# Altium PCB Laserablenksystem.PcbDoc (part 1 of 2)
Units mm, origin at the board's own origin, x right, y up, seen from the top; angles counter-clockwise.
Board outline 80 x 72 mm, 6 copper layers (L1 (Signal), L2 (GND), L3 (PWR), L4 (PWR), L5 (GND), L6 (Signal)), stack 1.637 mm thick; 152 components, 77 nets, 436 pads, 219 vias.
Unrouted connection lines stored in the file: 1.
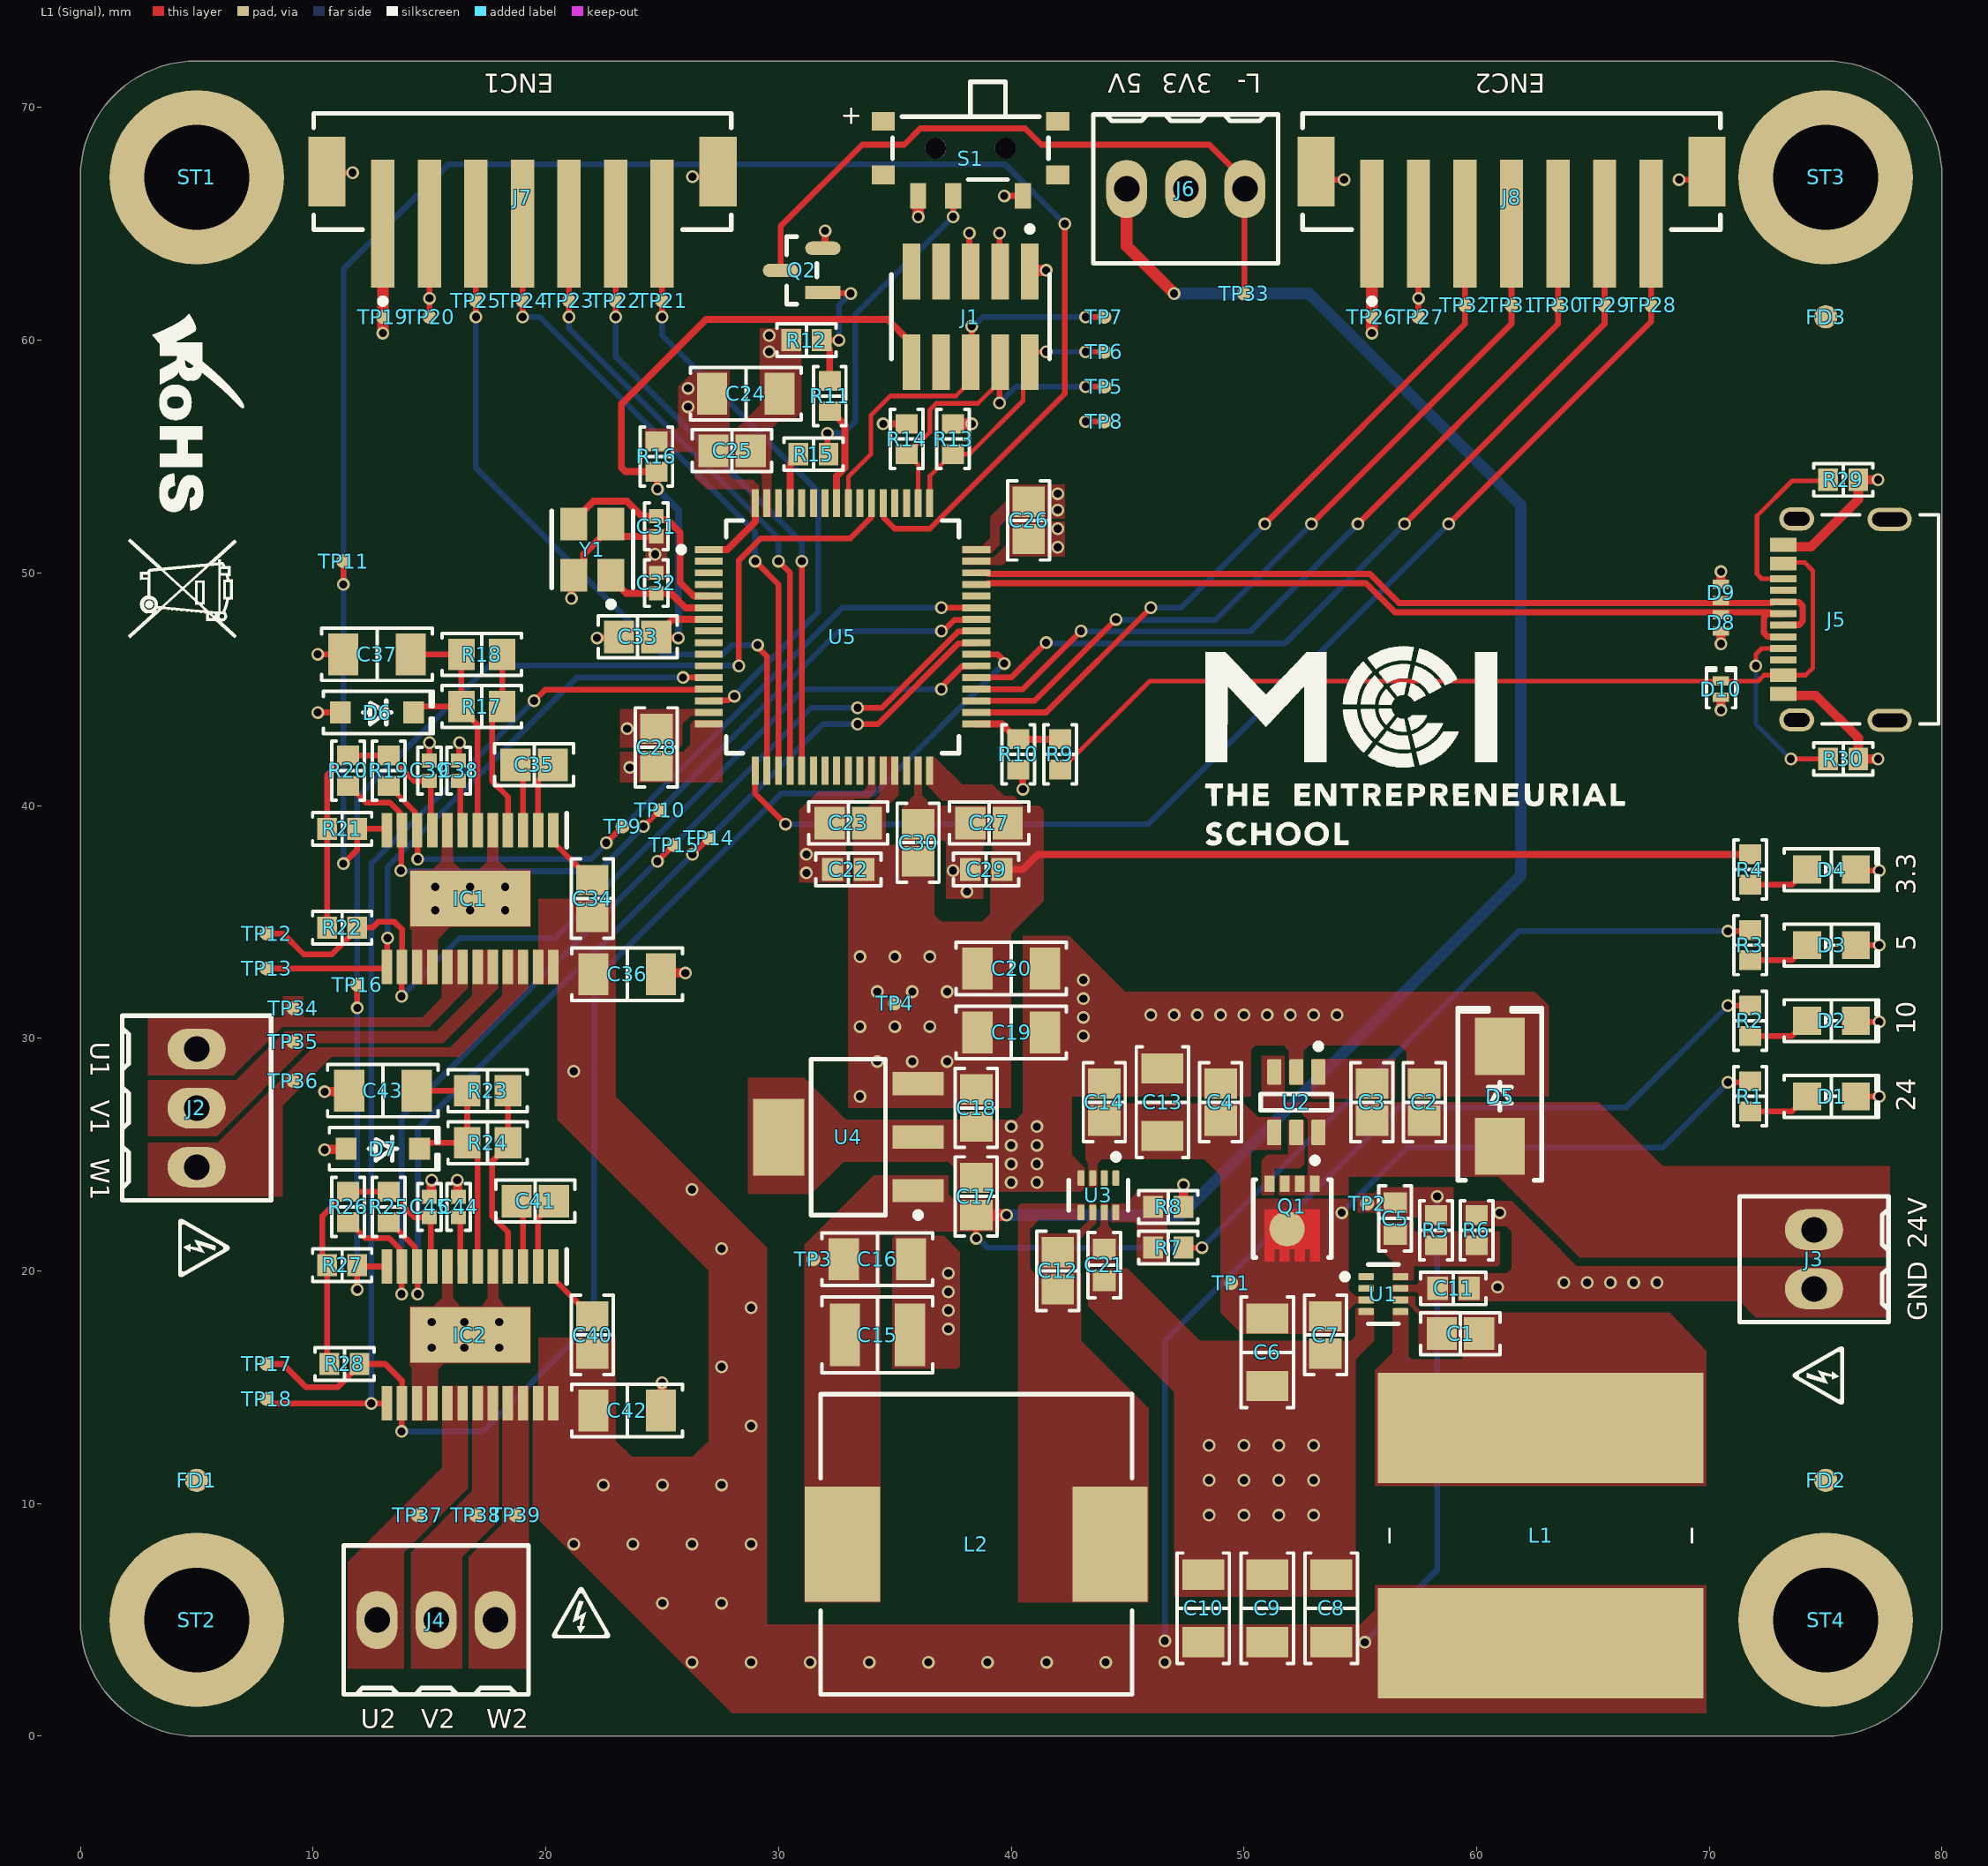
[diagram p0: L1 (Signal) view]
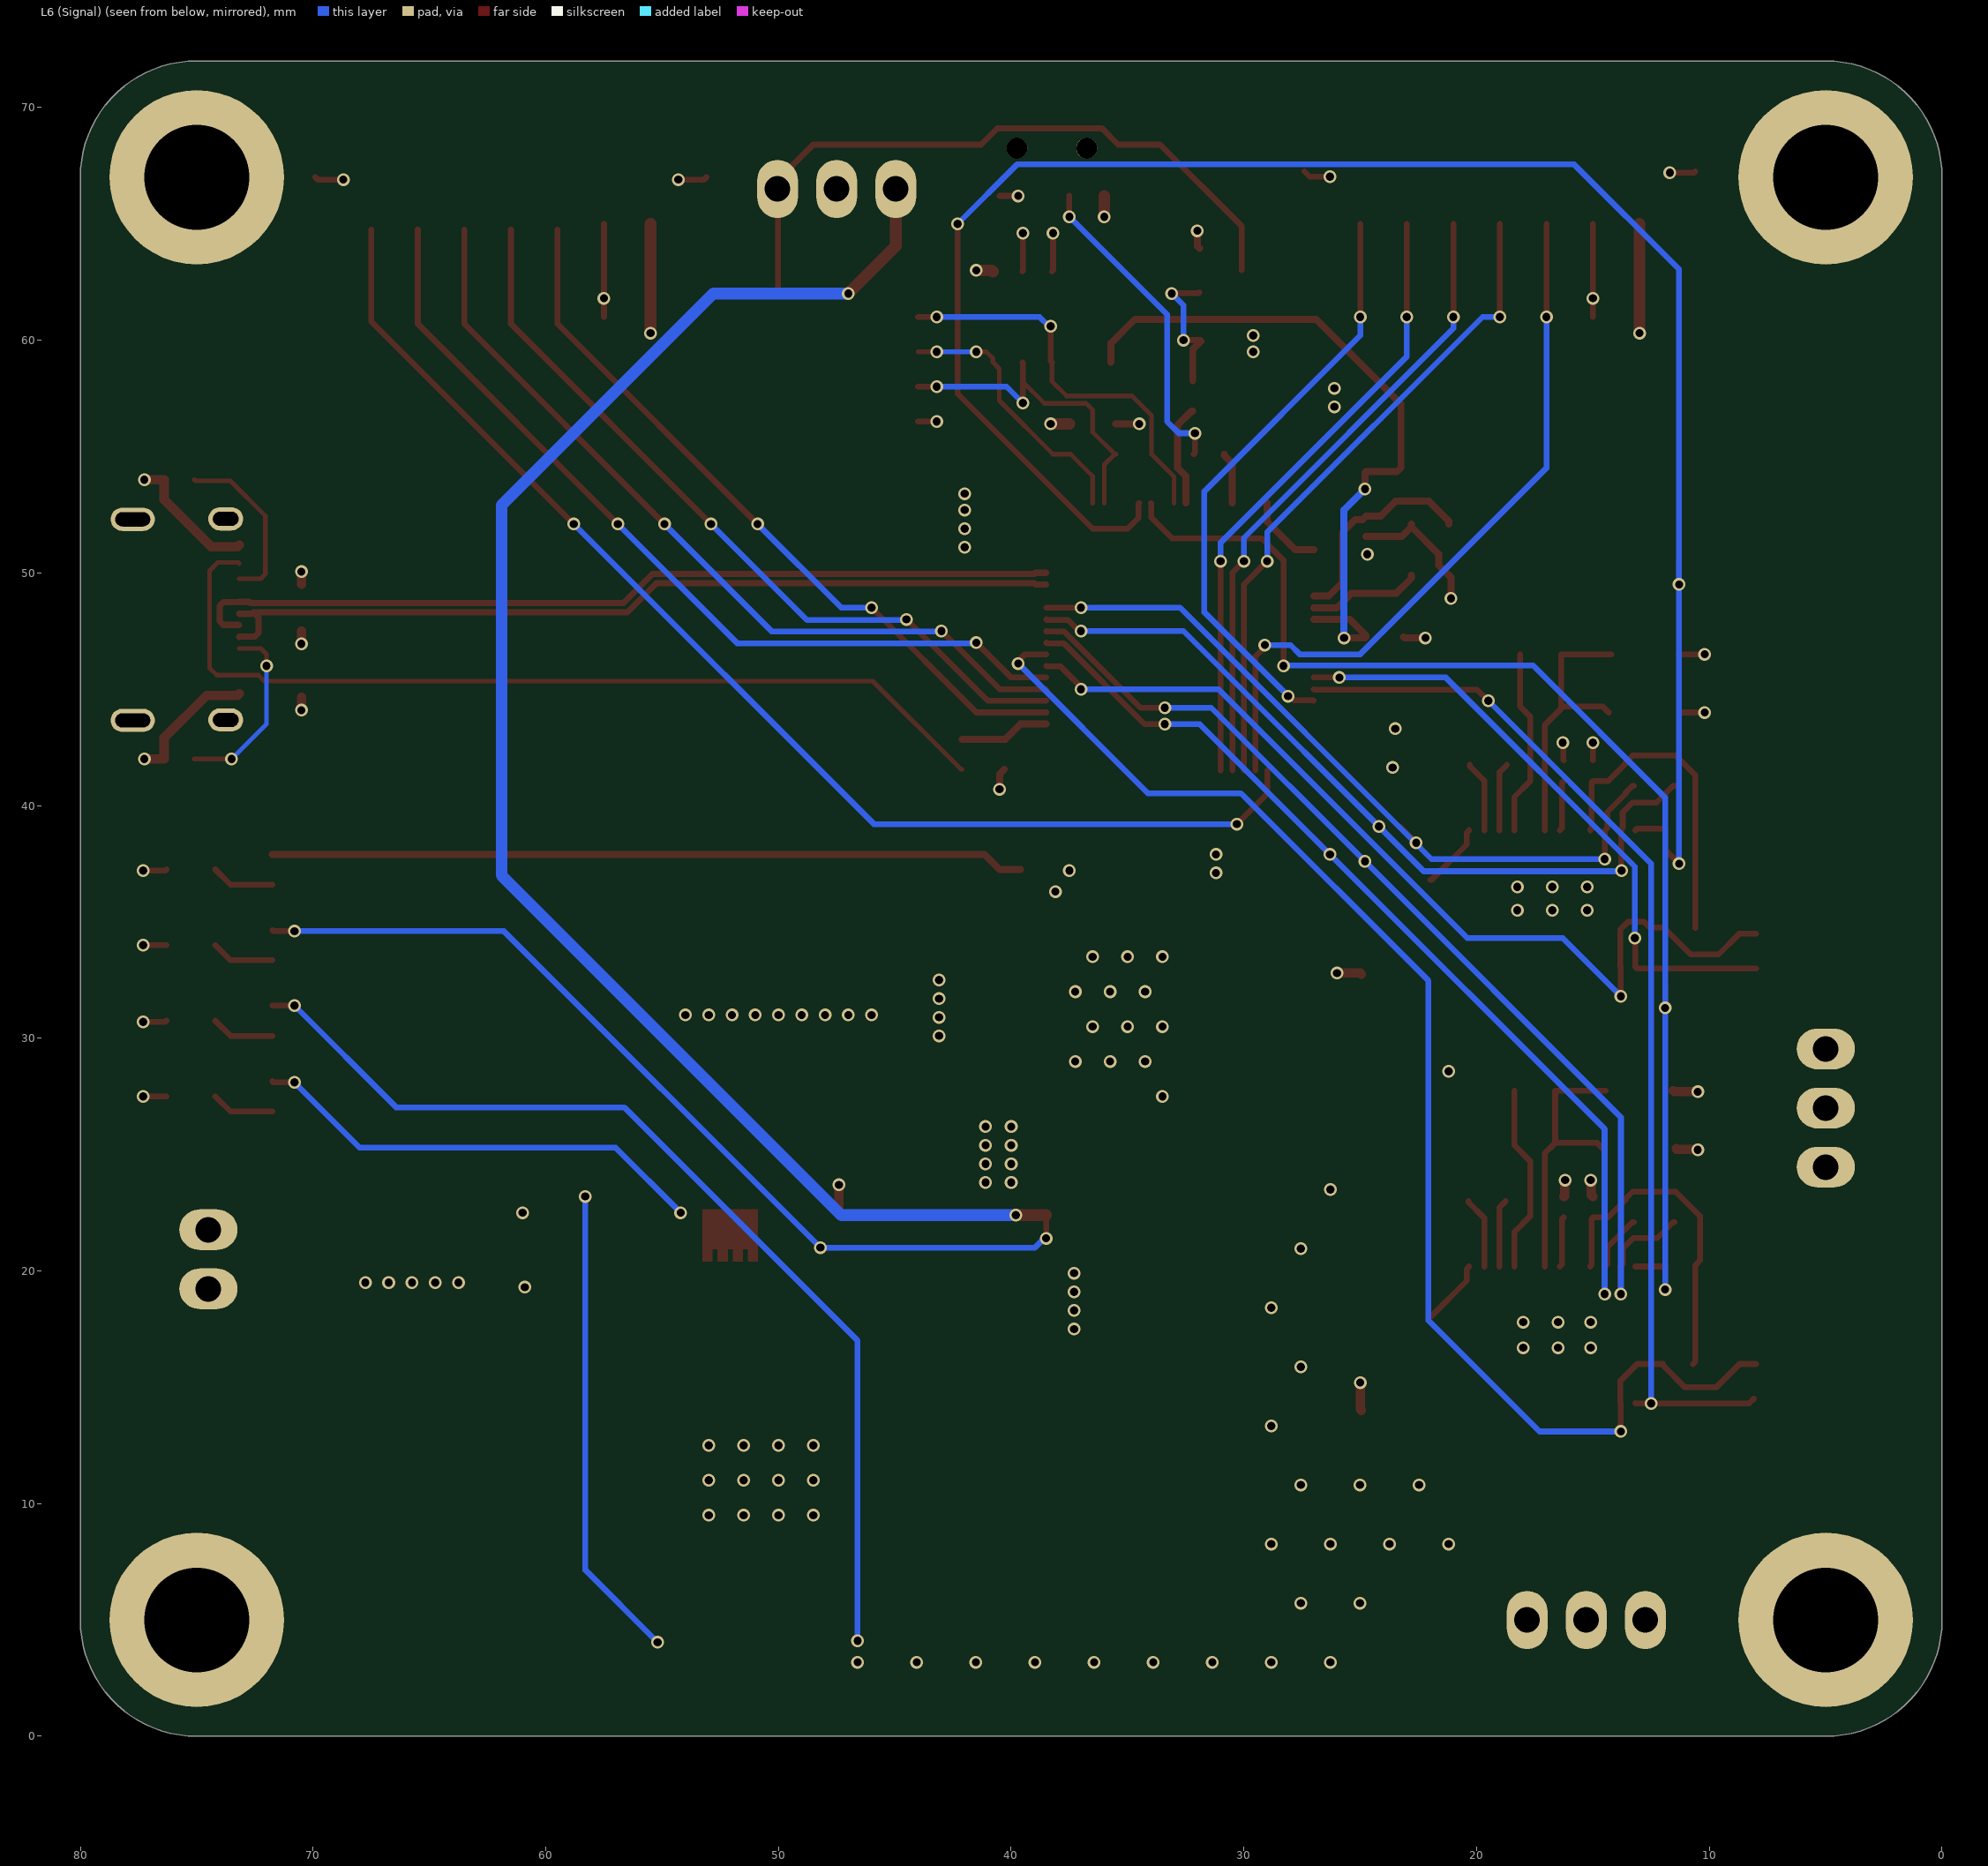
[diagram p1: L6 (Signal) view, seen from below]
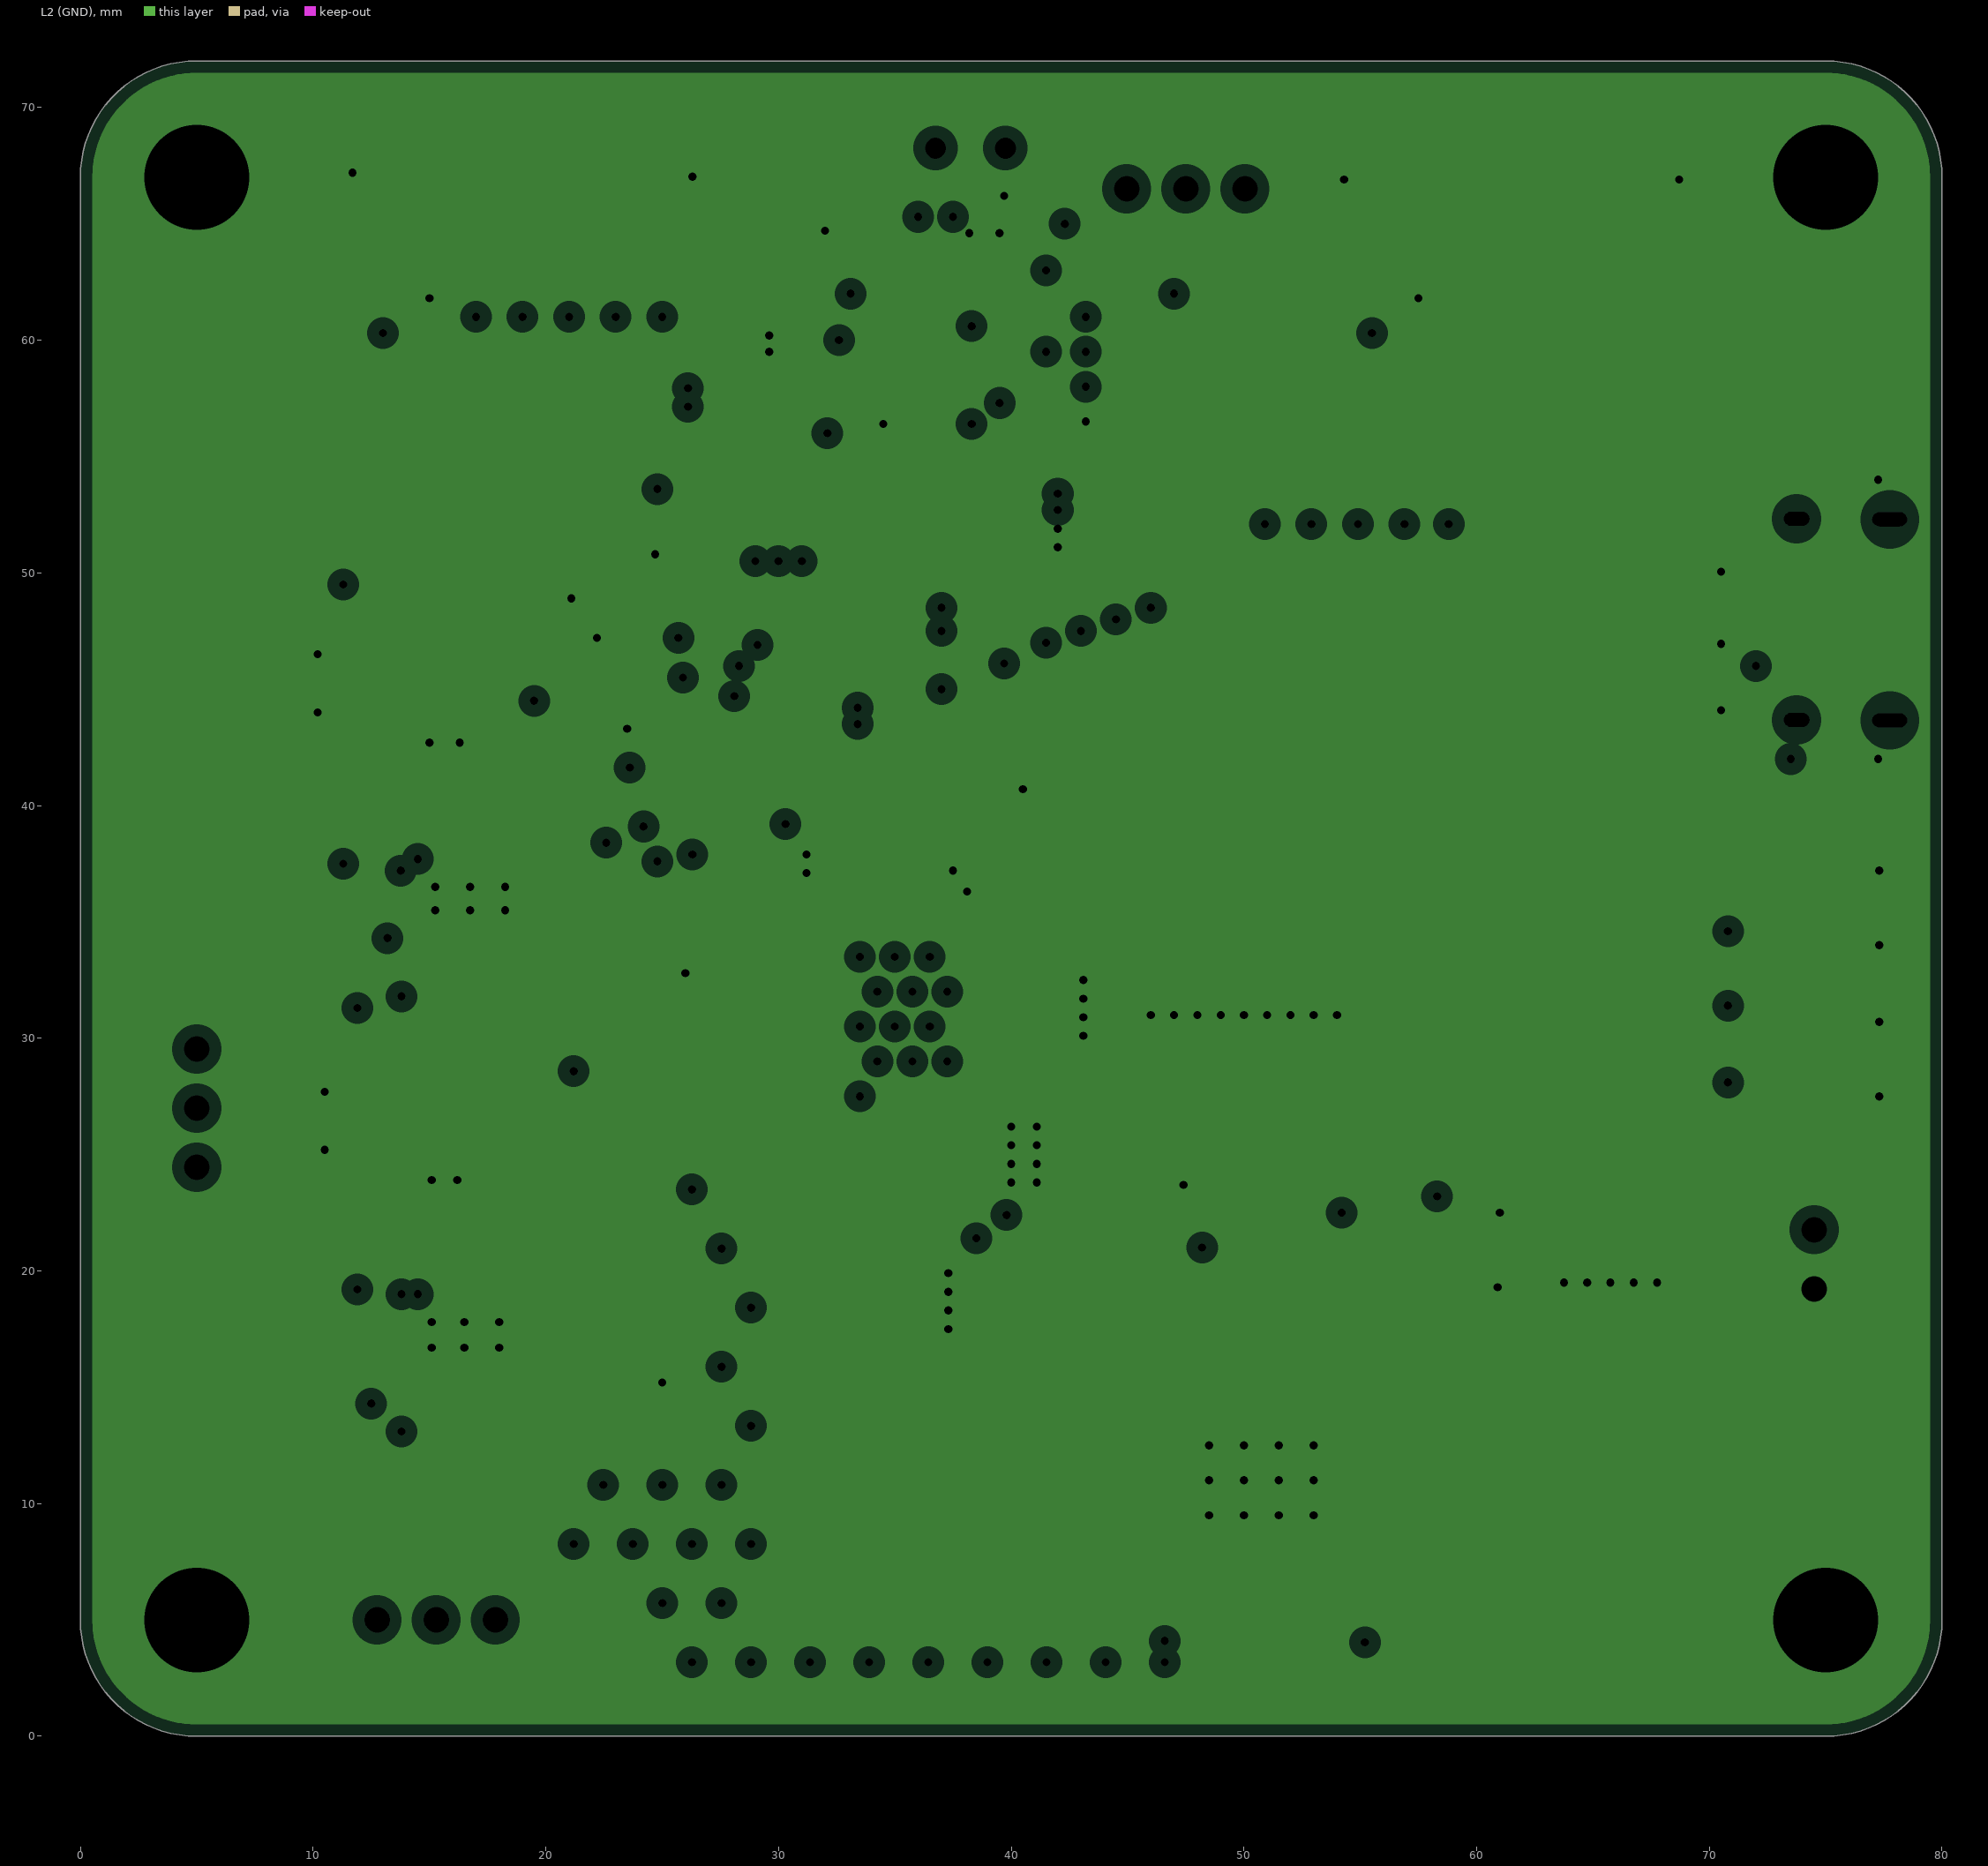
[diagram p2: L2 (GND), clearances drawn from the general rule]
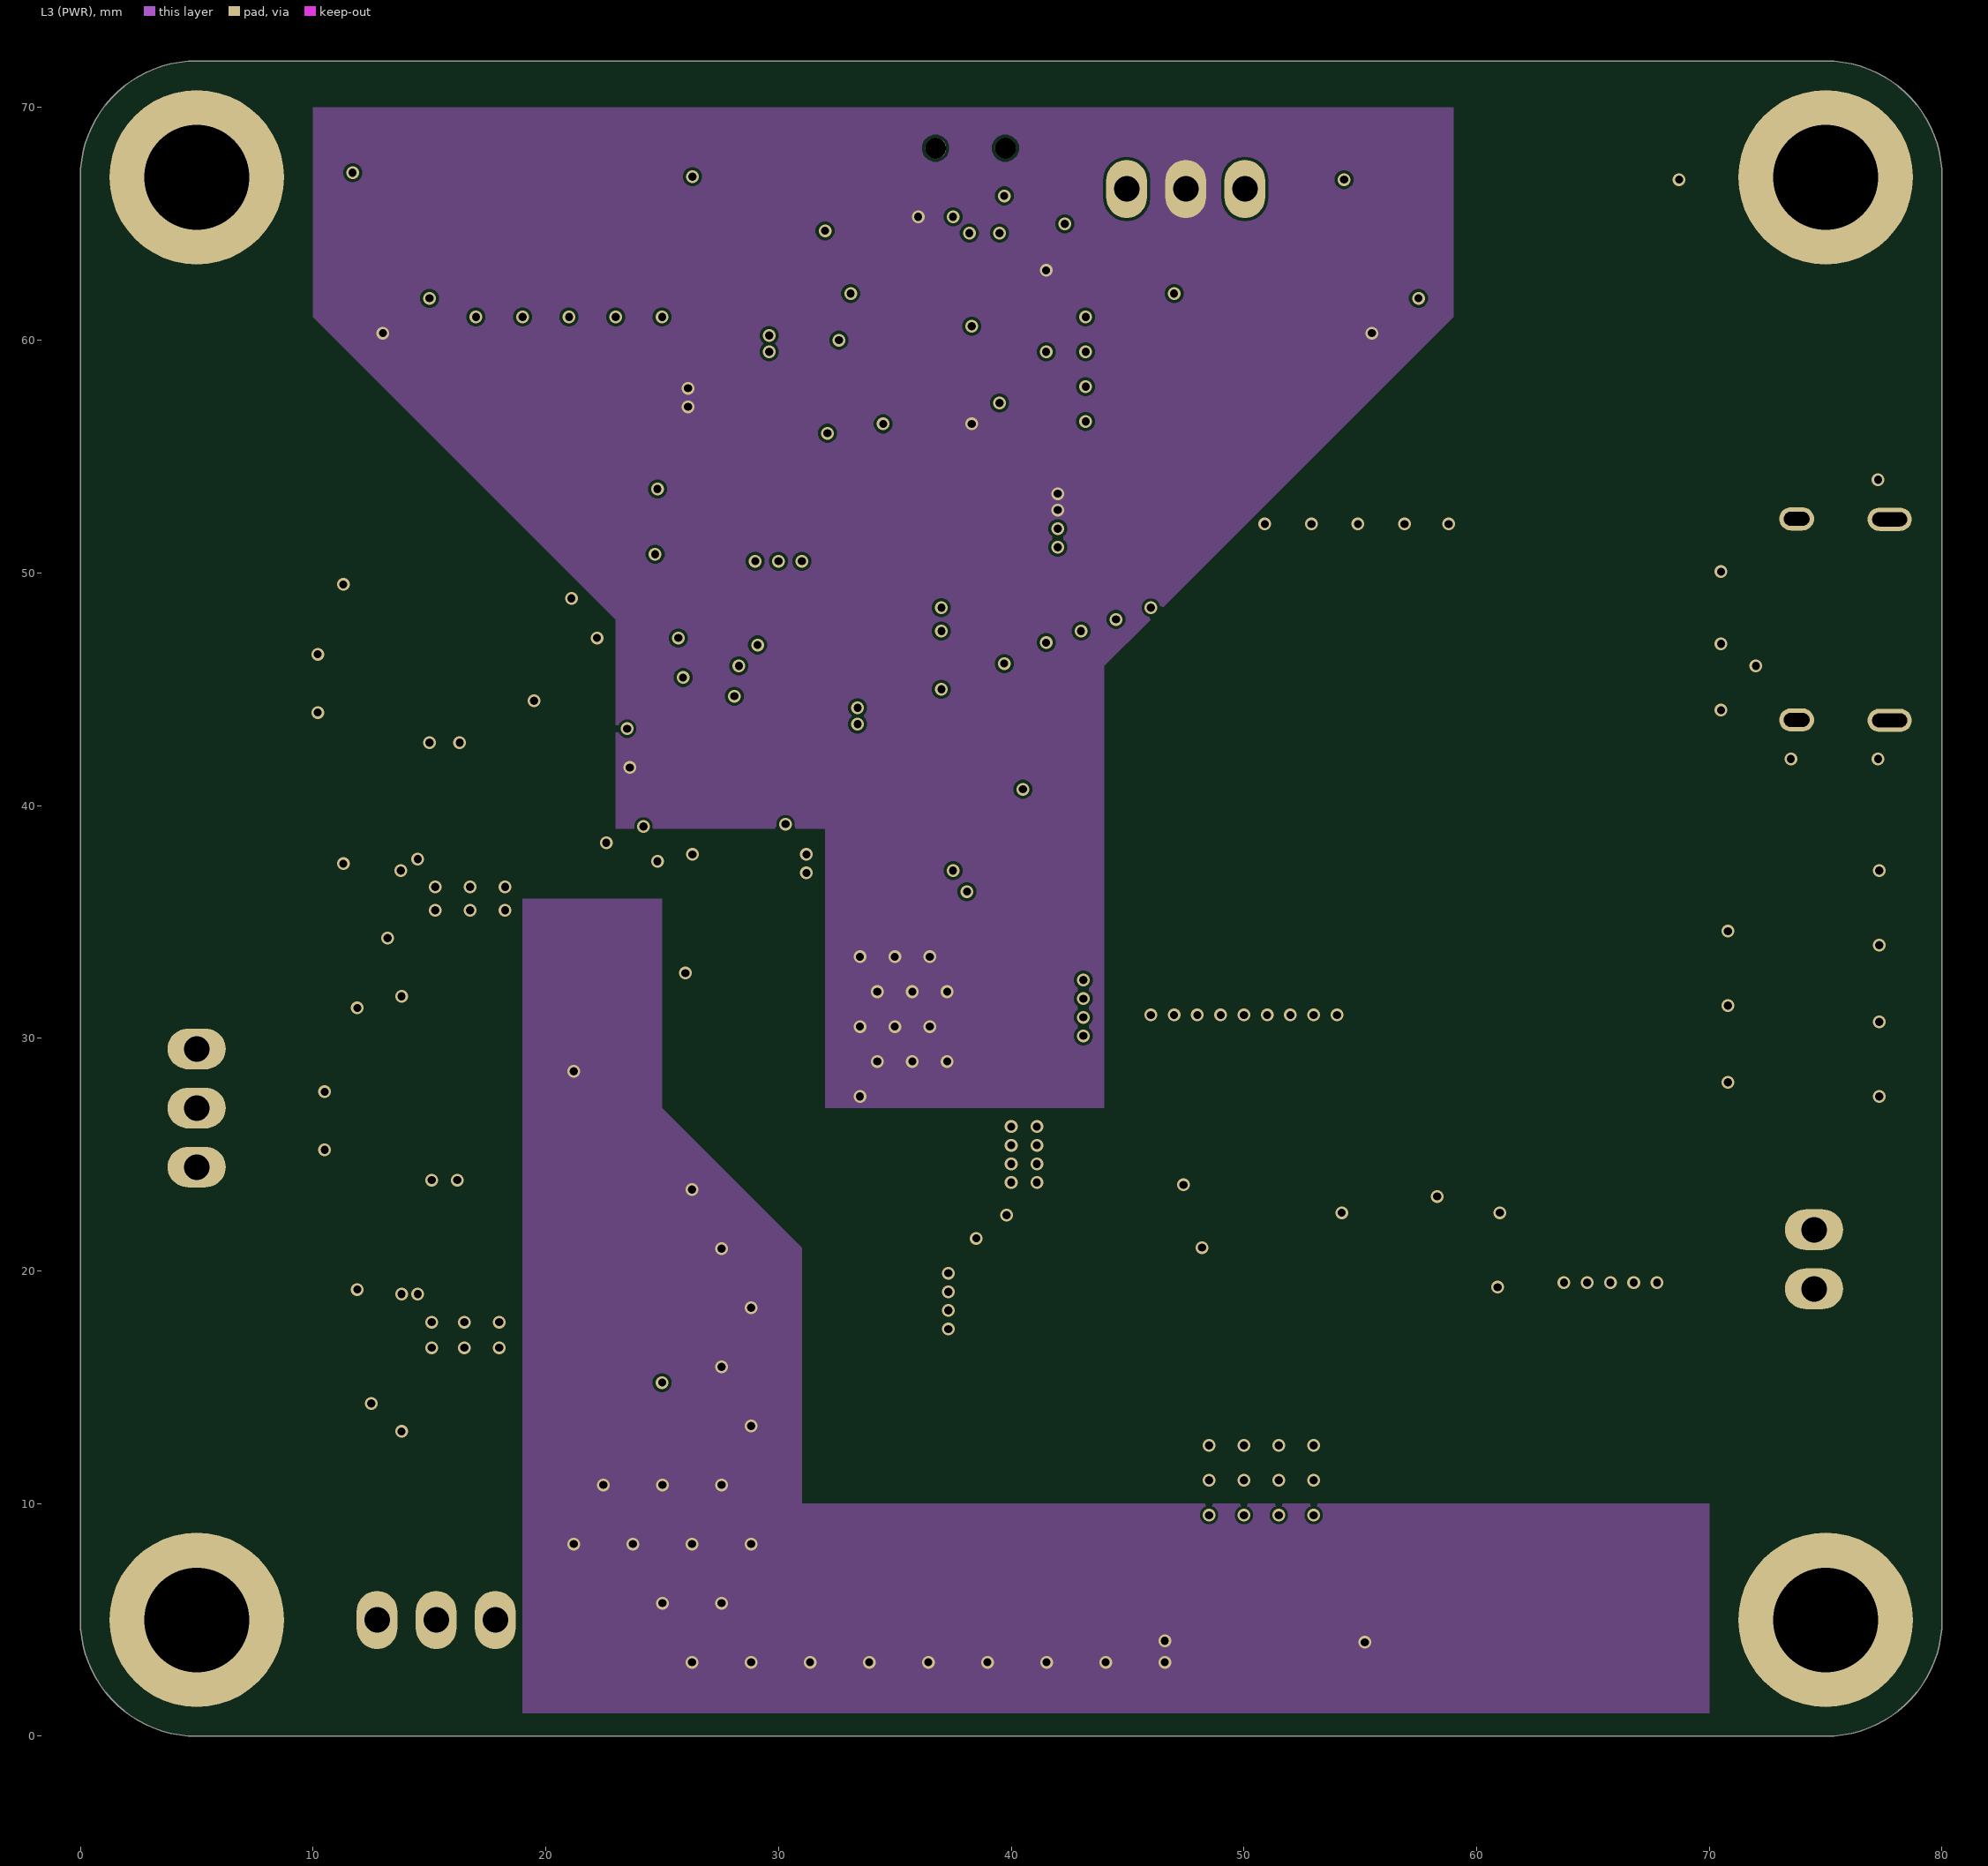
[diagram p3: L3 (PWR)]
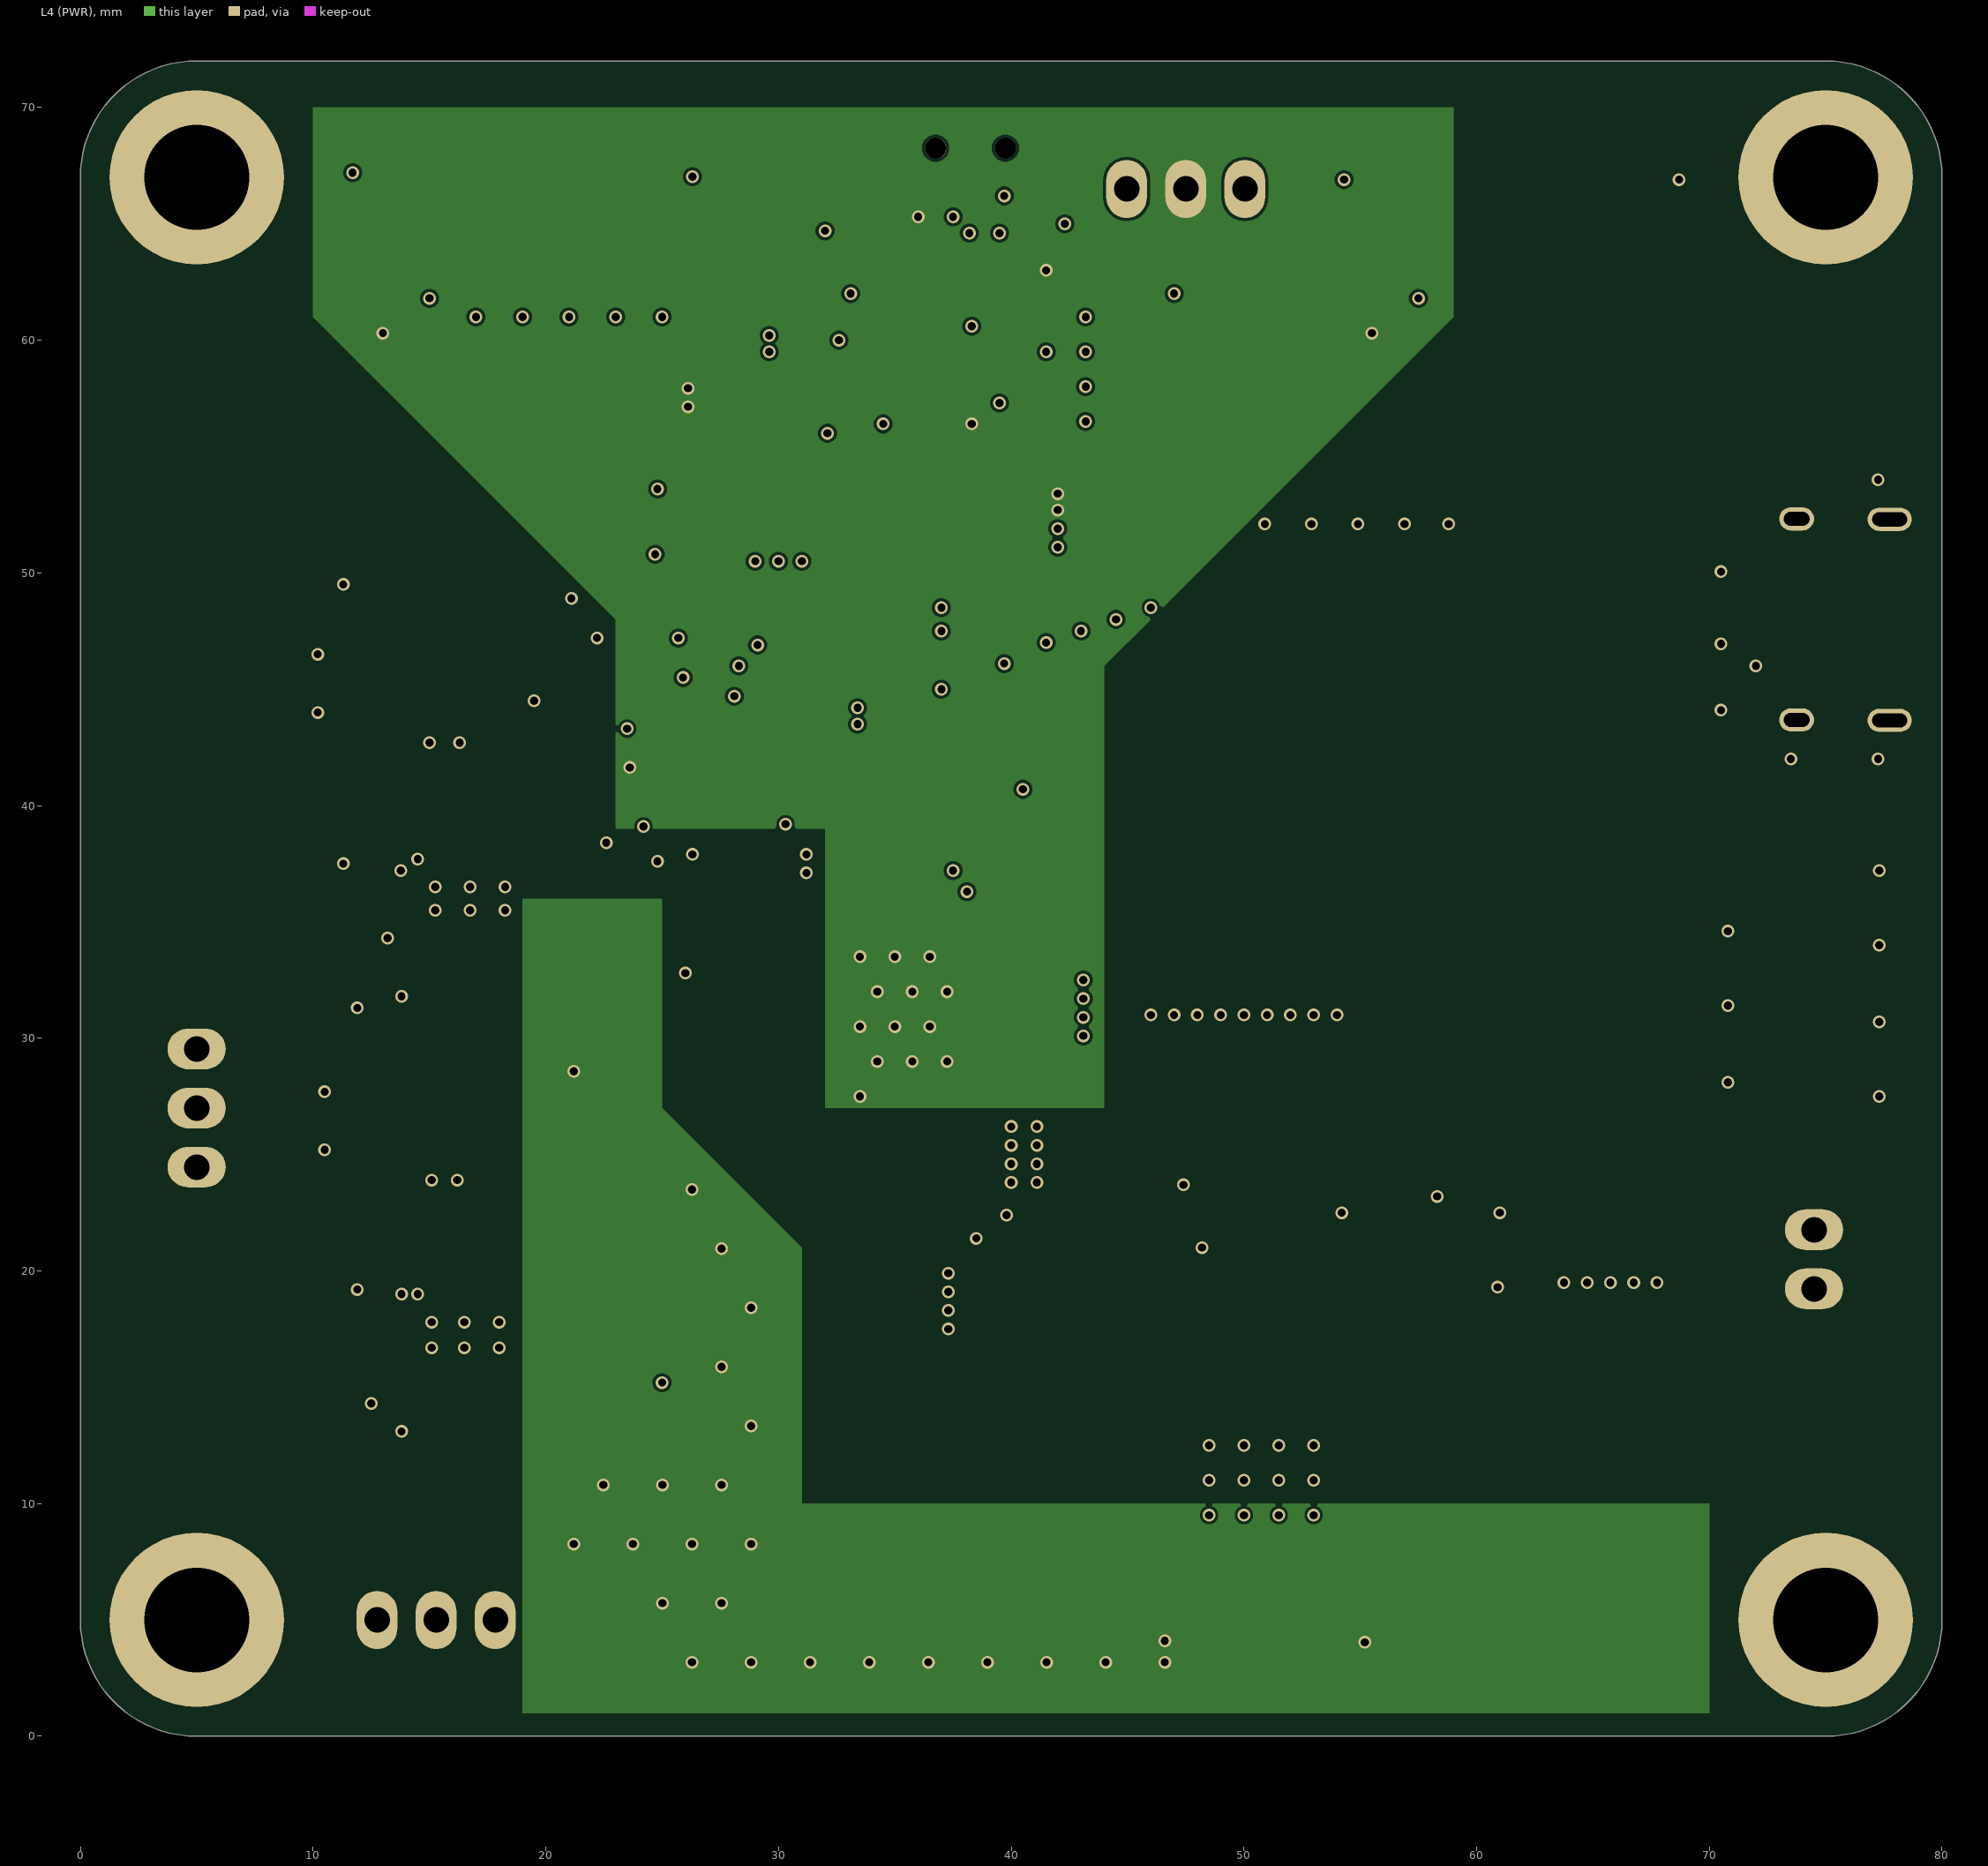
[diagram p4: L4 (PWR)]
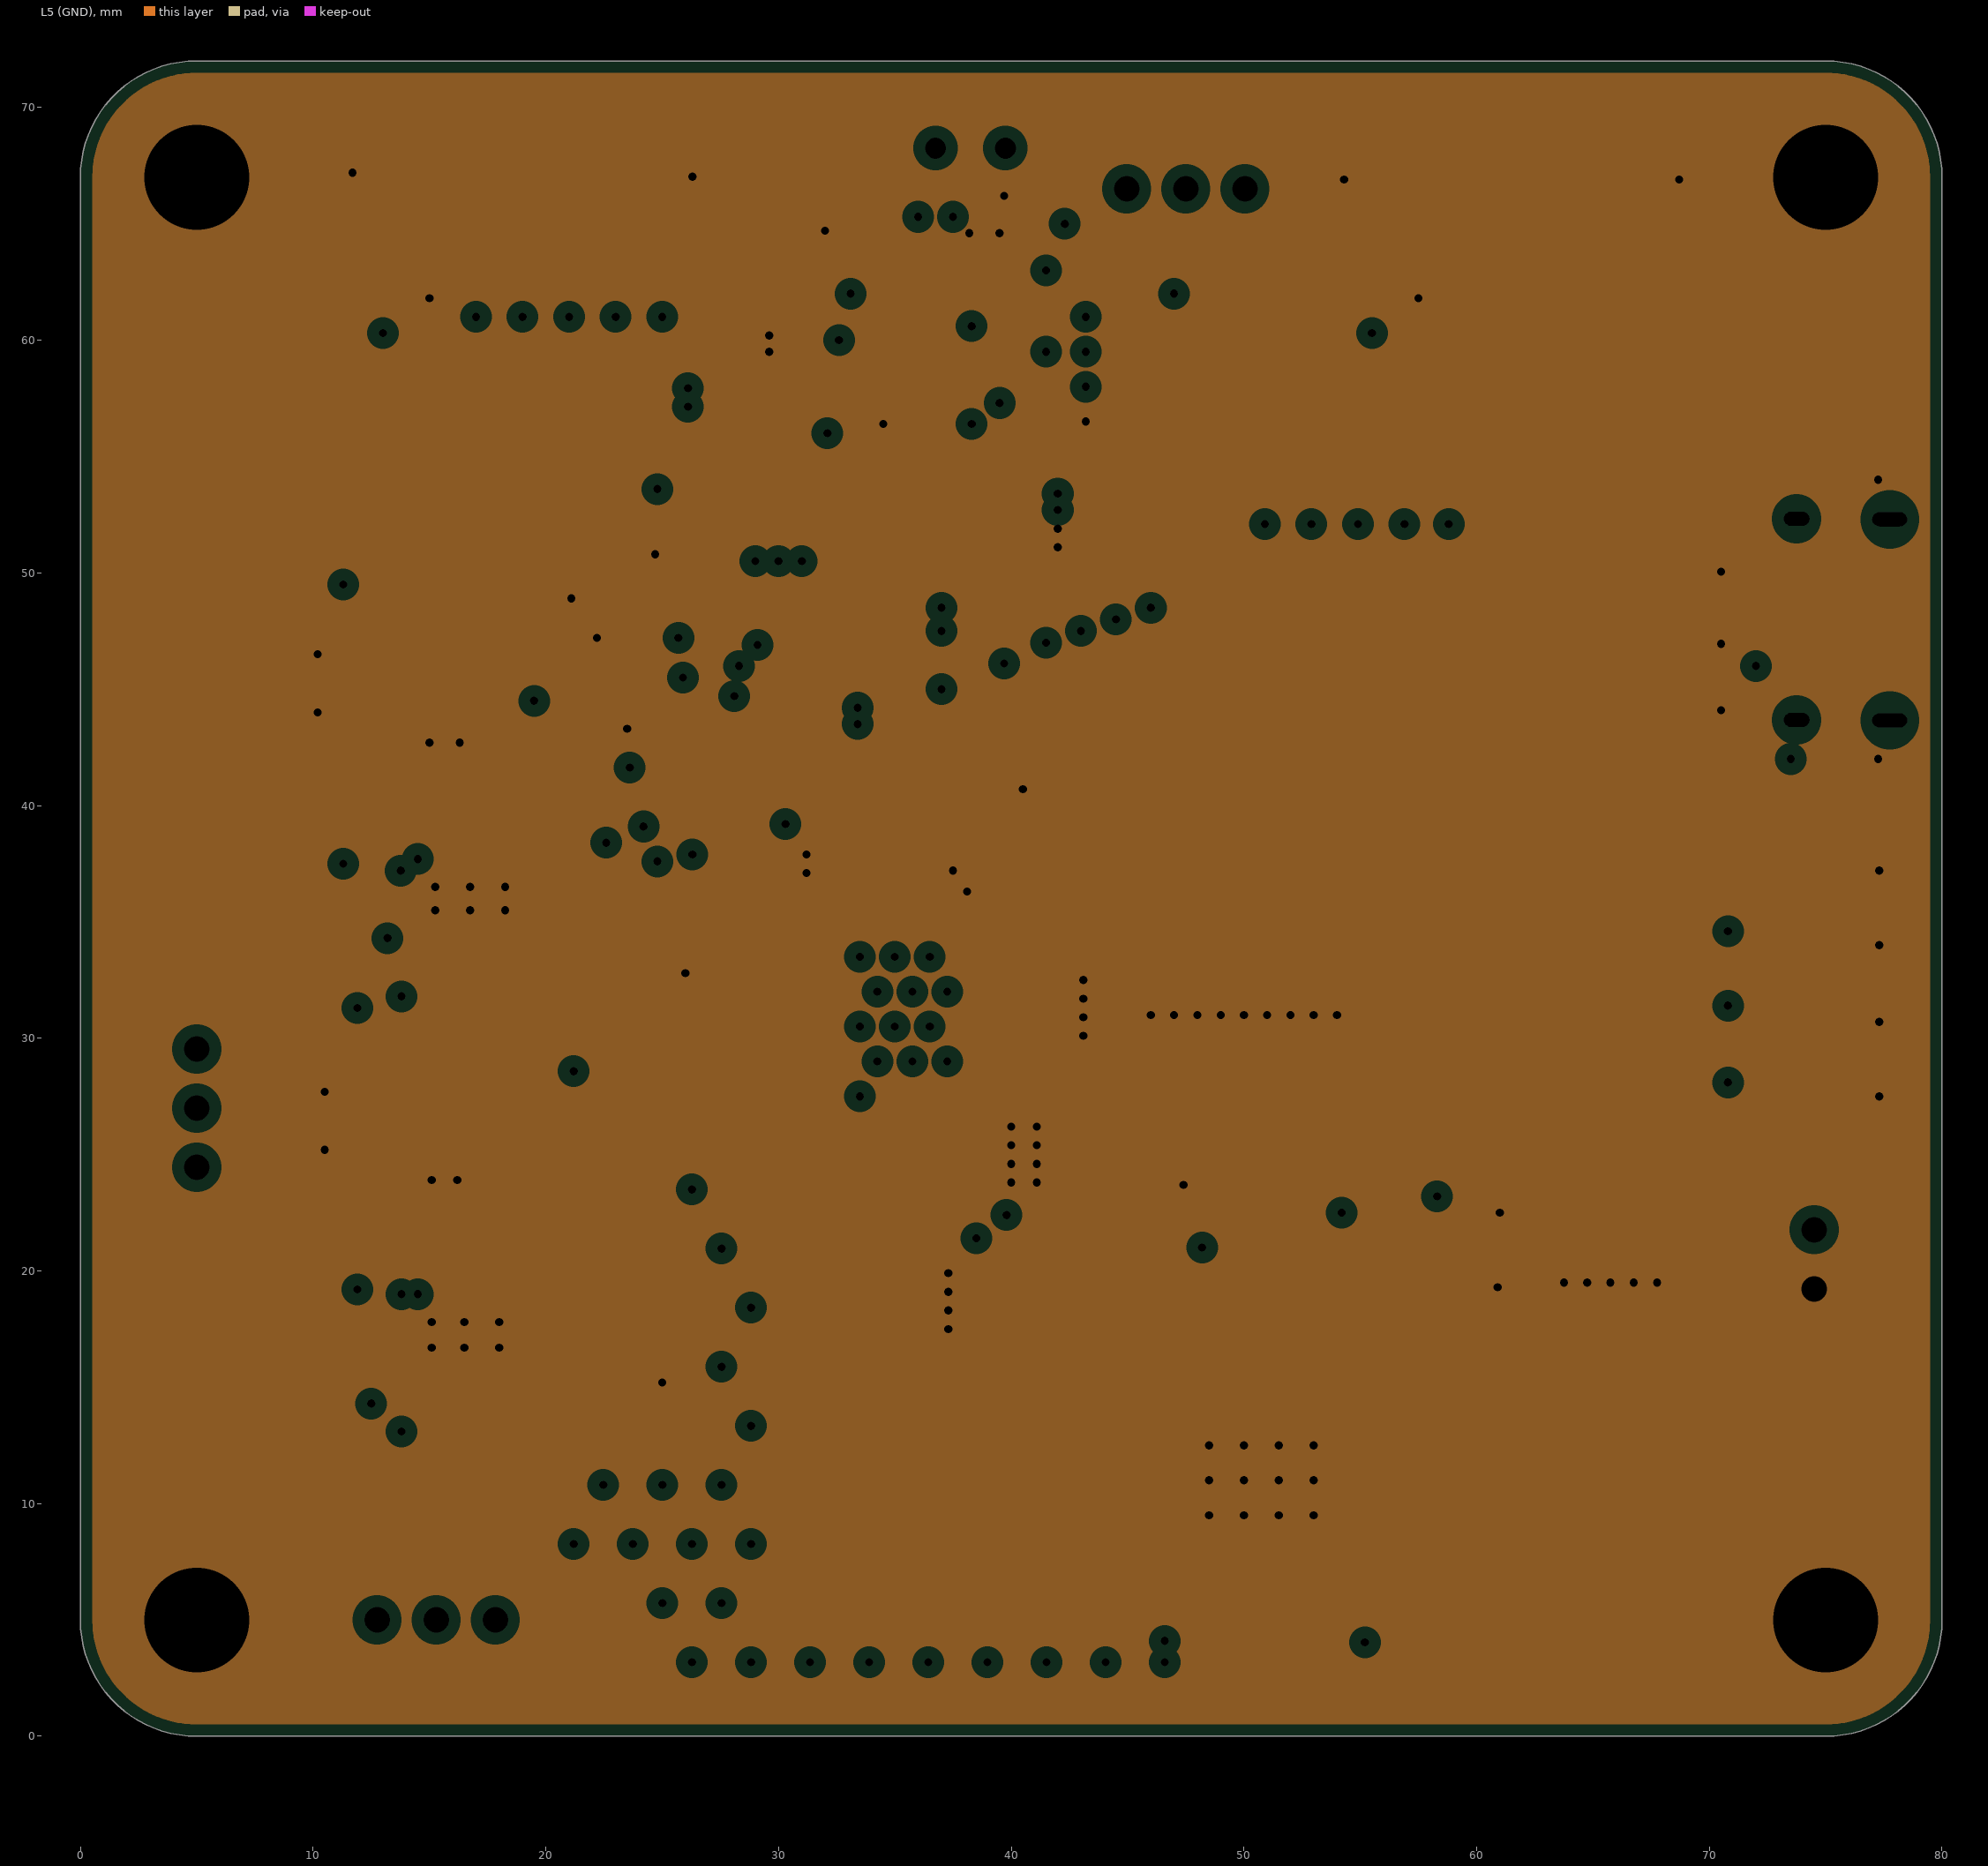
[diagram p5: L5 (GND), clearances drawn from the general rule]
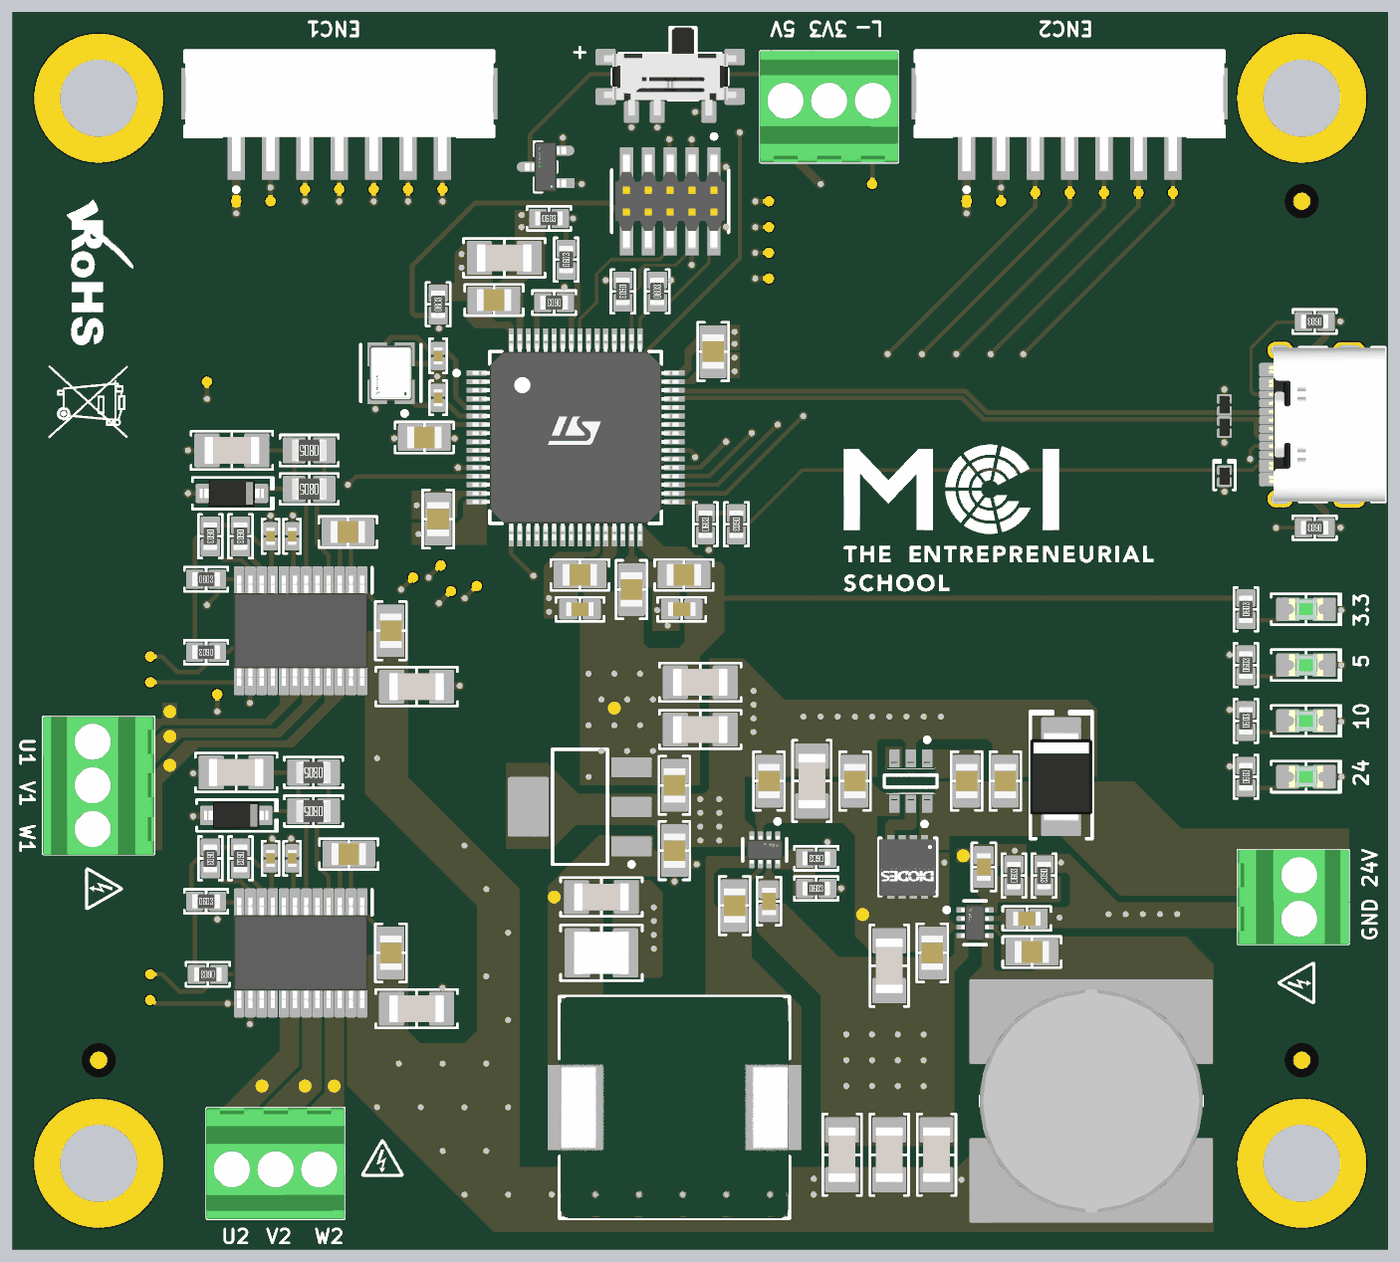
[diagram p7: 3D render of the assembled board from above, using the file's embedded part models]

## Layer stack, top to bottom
Top Solder: solder mask 0.0102, SM-001, Dk 3.5
L1 (Signal): signal copper 0.035
Dielectric 1: prepreg 0.1168, PP-016, Dk 4.25
Dielectric 2: prepreg 0.1168, PP-016, Dk 4.25
L2 (GND): plane copper 0.035, net GND
Dielectric 6: core 0.3048, Core-031, Dk 4.5
L3 (PWR): signal copper 0.035
Dielectric 8: prepreg 0.1168, PP-016, Dk 4.25
Dielectric 3: prepreg 0.1168, PP-016, Dk 4.25
Dielectric 9: prepreg 0.1168, PP-016, Dk 4.25
L4 (PWR): signal copper 0.035
Dielectric 7: core 0.3048, Core-031, Dk 4.5
L5 (GND): plane copper 0.035, net GND
Dielectric 4: prepreg 0.1168, PP-016, Dk 4.25
Dielectric 5: prepreg 0.1168, PP-016, Dk 4.25
L6 (Signal): signal copper 0.035
Bottom Solder: solder mask 0.0102, SM-001, Dk 3.5

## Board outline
0,5 0,50 0,67 cw(c5,67) 5,72 75,72 cw(c75,67) 80,67 80,5 cw(c75,5) 75,0 5,0 cw(c5,5)

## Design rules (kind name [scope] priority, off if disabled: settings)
Clearance [All] p1: gap=0.125 ignorepadtopadclearanceinfootprint=FALSE
DiffPairsRouting [All] p1: maxlimit=0.127 minlimit=0.127 mostfreqgap=0.127 toplayer_minwidth=0.27 toplayer_maxwidth=0.27 toplayer_prefwidth=0.27 midlayer1_minwidth=0.117 midlayer1_maxwidth=0.117 midlayer1_prefwidth=0.117 midlayer2_minwidth=0.117 midlayer2_maxwidth=0.117 midlayer2_prefwidth=0.117 bottomlayer_minwidth=0.27 bottomlayer_maxwidth=0.27 bottomlayer_prefwidth=0.27 impedanceprofiledriven=TRUE impedanceprofileid={E5E5535A-0CD5-4FF6-9C24-78283E052FCD} impedanceprofilevalue=90.000000 maxuncoupledlength=12.7
HoleSize HoleSizeVia [IsVia] p1: absolutevalues=TRUE maxlimit=0.45 minlimit=0.25 maxpercent=80.000 minpercent=20.000
HoleSize HoleSizePTH [IsPad] p2: absolutevalues=TRUE maxlimit=5.6 minlimit=0.5 maxpercent=80.000 minpercent=20.000
HoleToHoleClearance [All] p1: gap=0.3 allowstackedmicrovias=TRUE
MinimumAnnularRing MinimumAnnularRingVias [All] p1: minimumring=0.1
MinimumAnnularRing MinimumAnnularRingGeneral [All] p2: minimumring=0.3
MinimumSolderMaskSliver [All] p1: minsoldermaskwidth=0.08
PasteMaskExpansion [All] p1: expansion=0.085
PlaneClearance [All] p1: clearance=0.508
PlaneConnect [All] p1: planeconnectstyle=Direct reliefexpansion=0.508 reliefentries=4 reliefconductorwidth=0.254 reliefairgap=0.254
PolygonConnect [All] p1: connectstyle=Direct reliefconductorwidth=0.254 reliefentries=4 polygonreliefangle="90 Angle" airgapwidth=0.254
RoutingVias [All] p1: holewidth=0.35 width=0.55 viastyle="Through Hole" minholewidth=0.3 minwidth=0.5 maxholewidth=0.45 maxwidth=0.65
SilkToSilkClearance SilkToSilkClerance [All] p1: silktosilkclearance=0.125
SilkToSolderMaskClearance [IsPad] p1: minsilkscreentomaskgap=0.125 clearancetoexposedcopper=TRUE
SolderMaskExpansion SolderMaskExpansionVia [IsVia] p1: expansion=0.1 istentingtop=TRUE useseparateexpansions=TRUE expansionbottom=0.1 istentingbottom=TRUE
SolderMaskExpansion [All] p2: expansion=0.075 istentingtop=FALSE
SupplyNets "Schematic Supply Nets" [InNet('VCC3V3')] p1: voltage=0.000
SupplyNets "Schematic Supply Nets_6" [InNet('VCC24')] p2: voltage=0.000
SupplyNets "Schematic Supply Nets_5" [InNet('VCC5')] p3: voltage=0.000
SupplyNets "Schematic Supply Nets_3" [InNet('VCC10')] p4: voltage=0.000
SupplyNets "Schematic Supply Nets_1" [InNet('GND')] p5: voltage=0.000
UnRoutedNet [All] p1: checkbadconnections=TRUE
Width [All] p1: maxlimit=2.54 minlimit=0.125 preferedwidth=0.254
20 further rules are at their usual default settings.

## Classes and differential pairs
component class U_6_mech: FD1 FD2 FD3 ST1 ST2 ST3 ST4
component class U_5_conn: D8 D9 D10 J1 J2 J3 J4 J5 J6 J7 J8 R29 R30
component class U_4_motor-driver: C34 C35 C36 C37 C38 C39 C40 C41 C42 C43 C44 C45 D6 D7 IC1 IC2 R17 R18 R19 R20 R21 R22 R23 R24 R25 R26 R27 R28 TP34 TP35 TP36 TP37 TP38 TP39
component class U_3_mcu: C22 C23 C24 C25 C26 C27 C28 C29 C30 C31 C32 C33 Q2 R9 R10 R11 R12 R13 R14 R15 R16 S1 TP5 TP6 TP7 TP8 TP9 TP10 TP11 TP12 TP13 TP14 TP15 TP16 TP17 TP18 TP19 TP20 TP21 TP22 TP23 TP24 TP25 TP26 TP27 TP28 TP29 TP30 TP31 TP32 TP33 U5 Y1
component class U_2_power: C1 C2 C3 C4 C5 C6 C7 C8 C9 C10 C11 C12 C13 C14 C15 C16 C17 C18 C19 C20 C21 D5 L1 L2 Q1 R5 R6 R7 R8 TP1 TP2 TP3 TP4 U1 U2 U3 U4
component class 1_reference: D1 D2 D3 D4 R1 R2 R3 R4
differential pair USB: +USB_P -USB_N

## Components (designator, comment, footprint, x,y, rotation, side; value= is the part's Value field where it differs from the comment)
C1 "0.1 µF" "CAP 0805_2012" 59.3,17.3 r180 top
C2 "0.047µF" "CAP 0805_2012" 57.75,27.25 r270 top
C3 "0.1 µF" "CAP 0805_2012" 55.5,27.25 r270 top
C4 "0.1 µF" "CAP 0805_2012" 49,27.25 r270 top
C5 "1.5 pF" "CAP 0603_1608" 56.5,22.25 r90 top
C6 "10 µF" "CAP 1206_3216 - 0.8MM" 51,16.5 r90 top
C7 "0.1 µF" "CAP 0805_2012" 53.5,17.25 r90 top
C8 "10 µF" "CAP 1206_3216 - 0.8MM" 53.75,5.5 r270 top
C9 "10 µF" "CAP 1206_3216 - 0.8MM" 51,5.5 r270 top
C10 "10 µF" "CAP 1206_3216 - 0.8MM" 48.25,5.5 r270 top
C11 "0.033 µF" "CAP 0603_1608" 59,19.25 r180 top
C12 "0.1 µF" "CAP 0805_2012" 42,20 r90 top
C13 "10 µF" "CAP 1206_3216 - 0.8MM" 46.5,27.25 r270 top
C14 "0.1 µF" "CAP 0805_2012" 44,27.25 r270 top
C15 "47u" "CAP 1210_3225 - 1MM" 34.25,17.25 r180 top
C16 "10 µF" "CAP 1206_3216 - 0.8MM" 34.25,20.5 r180 top
C17 "0.1 µF" "CAP 0805_2012" 38.5,23.2 r270 top
C18 "0.1 µF" "CAP 0805_2012" 38.5,27 r90 top
C19 "10 µF" "CAP 1206_3216 - 0.8MM" 40,30.25 r180 top
C20 "10 µF" "CAP 1206_3216 - 0.8MM" 40,33 r180 top
C21 "0.033 µF" "CAP 0603_1608" 44,20.25 r90 top
C22 "1 µF" "CAP 0603_1608" 33,37.25 r0 top
C23 "0.1 µF" "CAP 0805_2012" 33,39.25 r0 top
C24 "4.7 µF" "CAP 1206_3216 - 0.8MM" 28.6,57.7 r180 top
C25 "0.1 µF" "CAP 0805_2012" 28,55.25 r180 top
C26 "0.1 µF" "CAP 0805_2012" 40.75,52.25 r90 top
C27 "0.1 µF" "CAP 0805_2012" 39.05,39.25 r0 top
C28 "0.1 µF" "CAP 0805_2012" 24.75,42.5 r270 top
C29 "1 µF" "CAP 0603_1608" 38.925,37.25 r0 top
C30 "0.1 µF" "CAP 0805_2012" 36,38.4 r270 top
C31 "9 pF" "CAP 0402_1005" 24.75,52 r90 top
C32 "9 pF" "CAP 0402_1005" 24.75,49.56 r270 top
C33 "0.1 µF" "CAP 0805_2012" 23.95,47.25 r0 top
C34 "0.1 µF" "CAP 0805_2012" 22,36 r90 top
C35 "0.1 µF" "CAP 0805_2012" 19.5,41.75 r180 top
C36 "10 µF" "CAP 1206_3216 - 0.8MM" 23.5,32.75 r0 top
C37 "10 µF" "CAP 1206_3216 - 0.8MM" 12.75,46.5 r0 top
C38 "1 µF" "CAP 0402_1005" 16.25,41.5 r90 top
C39 "1 µF" "CAP 0402_1005" 15,41.5 r90 top
C40 "0.1 µF" "CAP 0805_2012" 22,17.25 r90 top
C41 "0.1 µF" "CAP 0805_2012" 19.55,23 r180 top
C42 "10 µF" "CAP 1206_3216 - 0.8MM" 23.5,14 r0 top
C43 "10 µF" "CAP 1206_3216 - 0.8MM" 13,27.75 r0 top
C44 "1 µF" "CAP 0402_1005" 16.25,22.75 r90 top
C45 "1 µF" "CAP 0402_1005" 15,22.75 r90 top
D1 "Green" "LED 0805_2012 GREEN" 75.25,27.5 r0 top
D2 "Green" "LED 0805_2012 GREEN" 75.25,30.75 r0 top
D3 "Green" "LED 0805_2012 GREEN" 75.25,34 r0 top
D4 "Green" "LED 0805_2012 GREEN" 75.25,37.25 r0 top
D5 "SMBJ28CA" "DO214AA SMB" 61,27.5 r90 top
D6 "PDZ3.9BGWX" SOD-123 12.75,44 r0 top
D7 "PDZ3.9BGWX" SOD-123 13,25.25 r0 top
D8 "ESD321DPYR" 0402 70.5,47.85 r90 top
D9 "ESD321DPYR" 0402 70.5,49.15 r270 top
D10 "TPD1E10B06DPYR" 0402 70.5,45 r90 top
FD1 "FID1X2R" FID1X2R 5,11 r0 top locked
FD2 "FID1X2R" FID1X2R 75,11 r90 top
FD3 "FID1X2R" FID1X2R 75,61 r90 top
IC1 "DRV10975ZPWPR" SOP65P640X120-25N 16.75,36 r270 top
IC2 "DRV10975ZPWPR" SOP65P640X120-25N 16.75,17.25 r270 top
J1 "20021121-00010C4LF" FP-20021121-00010C4LF-MFG 38.25,61 r180 top
J2 "282834-3" "TE 282834-3" 5,27 r90 top
J3 "282834-2" "TE 282834-2" 74.5,20.5 r270 top
J4 "282834-3" "TE 282834-3" 15.29,5 r180 top
J5 "UJ20-C-H-G-SMT-2-P16-TR" "Same Sky UJ20-C-H-G-SMT-2-P16-TR" 77.75,48 r90 top
J6 "282834-3" "TE 282834-3" 47.5,66.5 r0 top
J7 "B7B-PH-SM4-TB(LF)(SN)" FP-B7B-PH-SM4-TB_LF_SN-MFG 19,67.25 r0 top
J8 "B7B-PH-SM4-TB(LF)(SN)" FP-B7B-PH-SM4-TB_LF_SN-MFG 61.5,67.25 r0 top
L1 "SDR1307-120ML" SDR1307120ML 62.75,8.625 r0 top value=12u
L2 "IHLP5050EZER8R2M01" FP-IHLP-5050EZ-FP_3_226x4-MFG 38.5,8.25 r180 top value=8u2
Q1 "DMT6007LFGQ-13" FP-POWERDI3333-8-MFG 52.075,22.25 r180 top
Q2 "BSS138" FP-318-08-IPC_B 31,63 r180 top
R1 "22k" "RES 0603_1608" 71.75,27.5 r90 top
R2 "10k" "RES 0603_1608" 71.75,30.75 r90 top
R3 "4k7" "RES 0603_1608" 71.75,34 r90 top
R4 "2k2" "RES 0603_1608" 71.75,37.25 r90 top
R5 "115k" "RES 0603_1608" 58.25,21.75 r90 top
R6 "10k" "RES 0603_1608" 60,21.75 r270 top
R7 "52k3" "RES 0603_1608" 46.75,21 r0 top
R8 "10k" "RES 0603_1608" 46.75,22.75 r180 top
R9 "33k" "RES 0603_1608" 42.1,42.2 r270 top
R10 "82k" "RES 0603_1608" 40.3,42.2 r90 top
R11 "100" "RES 0603_1608" 32.2,57.6 r90 top
R12 "10k" "RES 0603_1608" 31.2,60 r0 top
R13 "10k" "RES 0603_1608" 37.5,55.75 r90 top
R14 "10k" "RES 0603_1608" 35.5,55.75 r270 top
R15 "10k" "RES 0603_1608" 31.5,55.1 r180 top
R16 "10k" "RES 0603_1608" 24.75,55 r90 top
R17 "78R7" "RES 0805_2012" 17.25,44.25 r180 top
R18 "78R7" "RES 0805_2012" 17.25,46.5 r180 top
R19 "4k75" "RES 0603_1608" 13.25,41.5 r270 top
R20 "4k75" "RES 0603_1608" 11.5,41.5 r270 top
R21 "4k75" "RES 0603_1608" 11.25,39 r0 top
R22 "10k" "RES 0603_1608" 11.25,34.75 r180 top
R23 "78R7" "RES 0805_2012" 17.5,27.75 r180 top
R24 "78R7" "RES 0805_2012" 17.5,25.5 r180 top
R25 "4k75" "RES 0603_1608" 13.25,22.75 r270 top
R26 "4k75" "RES 0603_1608" 11.5,22.75 r270 top
R27 "4k75" "RES 0603_1608" 11.25,20.25 r0 top
R28 "10k" "RES 0603_1608" 11.35,16 r180 top
R29 "5k1" "RES 0603_1608" 75.75,54 r180 top
R30 "5k1" "RES 0603_1608" 75.75,42 r180 top
S1 "450404015514" "WURTH WS-SLSU 450404015514" 38.25,68.25 r0 top
ST1 "PTH-M4" PTH-M4-Footprint 5,67 r0 top
ST2 "PTH-M4" PTH-M4-Footprint 5,5 r0 top
ST3 "PTH-M4" PTH-M4-Footprint 75,67 r0 top
ST4 "PTH-M4" PTH-M4-Footprint 75,5 r0 top
TP1 "TPAD6R" TP06R 49.454,19.482 r90 top
TP2 "TPAD6R" TP06R 55.3,22.9 r90 top
TP3 "TPAD6R" TP06R 31.5,20.5 r90 top
TP4 "TPAD6R" TP06R 35,31.5 r90 top
TP5 "TPAD6R" TP06R 44,58 r90 top
TP6 "TPAD6R" TP06R 44,59.5 r90 top
TP7 "TPAD6R" TP06R 44,61 r90 top
TP8 "TPAD6R" TP06R 44,56.5 r90 top
TP9 "TPAD6R" TP06R 23.3,39.1 r90 top
TP10 "TPAD6R" TP06R 24.9,39.8 r90 top
TP11 "TPAD6R" TP06R 11.3,50.5 r90 top
TP12 "TPAD6R" TP06R 8,34.5 r90 top
TP13 "TPAD6R" TP06R 8,33 r90 top
TP14 "TPAD6R" TP06R 27,38.6 r90 top
TP15 "TPAD6R" TP06R 25.5,38.3 r90 top
TP16 "TPAD6R" TP06R 11.9,32.3 r90 top
TP17 "TPAD6R" TP06R 8,16 r90 top
TP18 "TPAD6R" TP06R 8,14.5 r90 top
TP19 "TPAD6R" TP06R 13,61 r90 top
TP20 "TPAD6R" TP06R 15,61 r90 top
TP21 "TPAD6R" TP06R 25,61.7 r90 top
TP22 "TPAD6R" TP06R 23,61.7 r90 top
TP23 "TPAD6R" TP06R 21,61.7 r90 top
TP24 "TPAD6R" TP06R 19,61.7 r90 top
TP25 "TPAD6R" TP06R 17,61.7 r90 top
TP26 "TPAD6R" TP06R 55.5,61 r90 top
TP27 "TPAD6R" TP06R 57.5,61 r90 top
TP28 "TPAD6R" TP06R 67.5,61.5 r90 top
TP29 "TPAD6R" TP06R 65.5,61.5 r90 top
TP30 "TPAD6R" TP06R 63.5,61.5 r90 top
TP31 "TPAD6R" TP06R 61.5,61.5 r90 top
TP32 "TPAD6R" TP06R 59.5,61.5 r90 top
TP33 "TPAD6R" TP06R 50,62 r90 top
TP34 "TPAD6R" TP06R 9.144,31.293 r90 top
TP35 "TPAD6R" TP06R 9.144,29.845 r90 top
TP36 "TPAD6R" TP06R 9.144,28.169 r90 top
TP37 "TPAD6R" TP06R 14.5,9.5 r90 top
TP38 "TPAD6R" TP06R 17,9.5 r90 top
TP39 "TPAD6R" TP06R 18.7,9.5 r90 top
U1 "TPS62933DRLR" FP-DRL0008A-MFG 55.99,19 r0 top
U2 "LM74700QDBVRQ1" FP-DBV0006A-MFG 52.25,27.25 r270 top
U3 "TPS62933DRLR" FP-DRL0008A-MFG 43.75,23.25 r270 top
U4 "MCP1825S-3302E/DB" SOT-223-DB3_N 33,25.75 r180 top
U5 "STM32G431RBT6" FP-LQFP64-5W-MFG 32.75,47.25 r0 top
Y1 "ABM8W-24.0000MHZ-8-D1X-T3" FP-ABM8W-MFG 22,51 r90 top

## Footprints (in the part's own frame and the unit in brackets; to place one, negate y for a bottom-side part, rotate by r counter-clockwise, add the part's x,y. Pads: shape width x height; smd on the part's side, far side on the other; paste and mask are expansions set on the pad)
0402 [mm] "SODFL, 2-Leads, Body 0.675x1.075mm, IPC Medium Density"
  rect 0.4x0.7 smd: 1(-0.35,0) 2(0.35,0)
  body extent -0.51,-0.31 0.5,0.3, height 0.45
"CAP 0402_1005" [mm] "Chip Capacitor, 2-Leads, Body 1.02x0.51mm, IPC Medium Density"
  rect 0.6x0.64 smd: 1(-0.44,0) 2(0.44,0)
  silkscreen extent -1,-0.5 1,0.5, body extent -0.5,-0.26 0.5,0.26, height 0.52
"CAP 0603_1608" [mm] "Chip Capacitor, 2-Leads, Body 1.60x0.80mm, IPC Medium Density"
  rect 0.9x1 smd: 1(-0.675,0) 2(0.675,0)
  silkscreen extent -1.4,-0.7 1.4,0.7, body extent -0.8,-0.41 0.8,0.41, height 0.82
"CAP 0805_2012" [mm] "Chip Capacitor, 2-Leads, Body 2.00x1.20mm, IPC Medium Density"
  rect 1.3x1.4 smd: 1(-0.8,0) 2(0.8,0)
  silkscreen extent -1.7,-0.9 1.7,0.9, body extent -1,-0.64 1,0.64, height 1.26
"CAP 1206_3216 - 0.8MM" [mm] "Chip Capacitor, 2-Leads, Body 3.25x1.60mm, IPC Medium Density"
  rect 1.3x1.8 smd: 1(-1.45,0) 2(1.45,0)
  silkscreen extent -2.37,-1.12 2.37,1.12, body extent -1.6,-0.8 1.6,0.8, height 0.8
"CAP 1210_3225 - 1MM" [mm] "Chip Capacitor, 2-Leads, Body 3.20x2.50mm, IPC Medium Density"
  rect 1.3x2.7 smd: 1(-1.4,0) 2(1.4,0)
  silkscreen extent -2.37,-1.63 2.37,1.63, body extent -1.6,-1.25 1.6,1.25, height 1
"DO214AA SMB" [mm] "Molded Diode, 2-Leads, Body 4.31x3.62mm, IPC Medium Density"
  rect 2.45x2.15 smd: 1(-2.15,0) 2(2.15,0)
  silkscreen extent -3.6,-1.8 3.8,1.8, body extent -2.6,-1.8 2.6,1.8, height 2.4
FID1X2R [mm] "Fiducial - Round 1x2mm"
  round 1 smd paste-2539.97 mask+0.5: 0(0,0)
FP-318-08-IPC_B [mm]
  rect 1.524x0.578 smd paste+0 mask+0: 1(-0.91,0.95)
  rrect100% 1.524x0.578 smd paste+0 mask+0: 2(-0.91,-0.95) 3(0.91,0)
  silkscreen extent -0.65,-1.45 0.65,1.45, body extent -1.92,-1.7 1.92,1.7, height 0.25
FP-20021121-00010C4LF-MFG [mm]
  rect 0.76x2.4 smd paste+0 mask+0: 1(-2.54,-1.95) 2(-2.54,1.95) 3(-1.27,-1.95) 4(-1.27,1.95) 5(0,-1.95) 6(0,1.95) 7(1.27,-1.95) 8(1.27,1.95) 9(2.54,-1.95) 10(2.54,1.95)
  silkscreen extent -3.4,-3.9 3.4,1.82, body extent -3.5,-3.25 3.5,3.25, height 0.25
FP-ABM8W-MFG [mm]
  rect 1.4x1.15 smd paste+0 mask+0: 1(-1.1,-0.8) 2(1.1,-0.8) 3(1.1,0.8) 4(-1.1,0.8)
  silkscreen extent -2.47,-1.75 1.65,1.75, body extent -1.9,-1.48 1.9,1.48, height 0.25
FP-B7B-PH-SM4-TB_LF_SN-MFG [mm]
  rect 1x5.5 smd paste+0 mask+0: 1(-6,-2.25) 2(-4,-2.25) 3(-2,-2.25) 4(0,-2.25) 5(2,-2.25) 6(4,-2.25) 7(6,-2.25)
  rect 1.6x3 smd paste+0 mask+0: 8(-8.4,0) 9(8.4,0)
  silkscreen extent -8.98,-5.7 8.98,2.5, body extent -9.3,-5.1 9.3,2.6, height 0.25
FP-DBV0006A-MFG [mm]
  rrect17% 1.1x0.6 smd paste+0 mask+0: 1(-1.3,0.95) 2(-1.3,0) 3(-1.3,-0.95) 4(1.3,-0.95) 5(1.3,0) 6(1.3,0.95)
  silkscreen extent -2.52,-1.53 0.35,1.53, body extent -1.95,-1.78 1.95,1.78, height 0.25
FP-DRL0008A-MFG [mm]
  rrect33% 0.67x0.3 smd paste+0 mask+0: 1(-0.74,0.75) 2(-0.74,0.25) 3(-0.74,-0.25) 4(-0.74,-0.75) 5(0.74,-0.75) 6(0.74,-0.25) 7(0.74,0.25) 8(0.74,0.75)
  silkscreen extent -1.77,-1.28 0.65,1.28, body extent -1.17,-1.35 1.17,1.35, height 0.25
FP-IHLP-5050EZ-FP_3_226x4-MFG [mil]
  rect 127.01x195 smd paste+0 mask+0: 1(-226.5,0) 2(226.5,0)
  silkscreen extent -264,-254 264,254, body extent -294,-258 294,258, height 10
FP-LQFP64-5W-MFG [mm]
  rect 1.2x0.3 smd paste+0 mask+0: 1(-5.75,3.75) 2(-5.75,3.25) 3(-5.75,2.75) 4(-5.75,2.25) 5(-5.75,1.75) 6(-5.75,1.25) 7(-5.75,0.75) 8(-5.75,0.25) 9(-5.75,-0.25) 10(-5.75,-0.75) 11(-5.75,-1.25) 12(-5.75,-1.75) 13(-5.75,-2.25) 14(-5.75,-2.75) 15(-5.75,-3.25) 16(-5.75,-3.75) 33(5.75,-3.75) 34(5.75,-3.25) 35(5.75,-2.75) 36(5.75,-2.25) 37(5.75,-1.75) 38(5.75,-1.25) 39(5.75,-0.75) 40(5.75,-0.25) 41(5.75,0.25) 42(5.75,0.75) 43(5.75,1.25) 44(5.75,1.75) 45(5.75,2.25) 46(5.75,2.75) 47(5.75,3.25) 48(5.75,3.75)
  rect 0.3x1.2 smd paste+0 mask+0: 17(-3.75,-5.75) 18(-3.25,-5.75) 19(-2.75,-5.75) 20(-2.25,-5.75) 21(-1.75,-5.75) 22(-1.25,-5.75) 23(-0.75,-5.75) 24(-0.25,-5.75) 25(0.25,-5.75) 26(0.75,-5.75) 27(1.25,-5.75) 28(1.75,-5.75) 29(2.25,-5.75) 30(2.75,-5.75) 31(3.25,-5.75) 32(3.75,-5.75) 49(3.75,5.75) 50(3.25,5.75) 51(2.75,5.75) 52(2.25,5.75) 53(1.75,5.75) 54(1.25,5.75) 55(0.75,5.75) 56(0.25,5.75) 57(-0.25,5.75) 58(-0.75,5.75) 59(-1.25,5.75) 60(-1.75,5.75) 61(-2.25,5.75) 62(-2.75,5.75) 63(-3.25,5.75) 64(-3.75,5.75)
  silkscreen extent -7.05,-5 5,5, body extent -6.45,-6.45 6.45,6.45, height 0.25
FP-POWERDI3333-8-MFG [mm]
  rect 0.42x0.7 smd paste+0 mask+0: 1(-0.975,-1.5) 2(-0.325,-1.5) 3(0.325,-1.5) 4(0.975,-1.5)
  round 1.519 smd paste+0 mask+0: 5-6-7-8(0.221,0.444)
  L1 (Signal) region: -1.185,1.85 -0.765,1.85 -0.765,1.31 -0.535,1.31 -0.535,1.85 -0.115,1.85 -0.115,1.31 0.115,1.31 0.115,1.85 0.535,1.85 0.535,1.31 0.765,1.31 0.765,1.85 1.185,1.85 1.185,-0.4 -1.185,-0.4
  silkscreen extent -1.68,-2.62 1.68,1.68, body extent -1.78,-1.95 1.78,1.95, height 0.25
"LED 0805_2012 GREEN" [mm] "Chip Diode, 2-Leads, Body 2.00x1.25mm, IPC Medium Density"
  rect 1.2x1.2 smd: 1(-1.05,0) 2(1.05,0)
  silkscreen extent -2.03,-0.9 2.03,0.9, body extent -1,-0.62 1,0.63, height 0.9
PTH-M4-Footprint [mm]
  round 7.5 hole 4.5: 1(0,0)
"RES 0603_1608" [mm] "Chip Resistor, 2-Leads, Body 1.60x0.80mm, IPC Medium Density"
  rect 0.85x0.95 smd: 1(-0.65,0) 2(0.65,0)
  silkscreen extent -1.27,-0.7 1.27,0.7, body extent -0.8,-0.4 0.8,0.4, height 0.45
"RES 0805_2012" [mm] "Chip Resistor, 2-Leads, Body 2.00x1.25mm, IPC Medium Density"
  rect 1.15x1.35 smd: 1(-0.875,0) 2(0.875,0)
  silkscreen extent -1.7,-0.9 1.7,0.9, body extent -1,-0.62 1,0.63, height 0.6
"Same Sky UJ20-C-H-G-SMT-2-P16-TR" [mm] "Type C, USB 2.0, 480 Mbps, 48 Vdc, 5 A, Horizontal, Surface Mount Anchor Pins Mounting Style, Surface Mount Contact Pin Type, Gold Plated 3 µin, 16 Pins, USB Receptacle"
  rect 0.6x1.15 smd: A1B12(-3.2,4.575) A4B9(-2.4,4.575) B1A12(3.2,4.575) B4A9(2.4,4.575)
  rect 0.3x1.15 smd: A5(-1.25,4.575) A6(-0.25,4.575) A7(0.25,4.575) A8(1.25,4.575) B5(1.75,4.575) B6(0.75,4.575) B7(-0.75,4.575) B8(-1.75,4.575)
  oval 1x1.9 hole 0.6 slot 1.5 at 90 deg: S(-4.34,0) S(4.3,0)
  oval 1x1.5 hole 0.6 slot 1.1 at 90 deg: S(-4.32,4) S(4.32,4)
  silkscreen extent -4.5,-2.1 4.5,2.9, body extent -4.47,-2.1 4.47,4.65, height 3.26
SDR1307120ML [mm]
  rect 14x4.75 smd: 1(0,4.625) 2(0,-4.625)
  silkscreen extent -6.5,-0.3 6.5,0.3, body extent -6.5,-6.5 6.5,6.5, height 7
SOD-123 [mm] "SOD, 2-Leads, Body 1.55x3.70mm, IPC Medium Density"
  rect 0.9x0.95 smd: 1(-1.575,0) 2(1.575,0)
  silkscreen extent -2.3,-0.92 2.41,0.92, body extent -1.86,-0.78 1.86,0.77, height 1.35
SOP65P640X120-25N [mm]
  rect 1.475x0.45 smd: 1(-2.938,3.575) 2(-2.938,2.925) 3(-2.938,2.275) 4(-2.938,1.625) 5(-2.938,0.975) 6(-2.938,0.325) 7(-2.938,-0.325) 8(-2.938,-0.975) 9(-2.938,-1.625) 10(-2.938,-2.275) 11(-2.938,-2.925) 12(-2.938,-3.575) 13(2.938,-3.575) 14(2.938,-2.925) 15(2.938,-2.275) 16(2.938,-1.625) 17(2.938,-0.975) 18(2.938,-0.325) 19(2.938,0.325) 20(2.938,0.975) 21(2.938,1.625) 22(2.938,2.275) 23(2.938,2.925) 24(2.938,3.575)
  rect 2.4x5.16 smd: 25(0,0)
  silkscreen extent -3.67,4.15 -2.2,4.15, body extent -3.21,-3.9 3.21,3.9, height 1
SOT-223-DB3_N [mm] "SOT223, 4-Leads, Body 6.5x3.5mm, Pitch 2.3mm, Lead Span 7mm, IPC Medium Density"
  rect 2.2x1 smd: 1(-3,2.3) 2(-3,0) 3(-3,-2.3)
  rect 2.2x3.3 smd: 4(3,0)
  silkscreen extent -3.13,-3.35 1.6,3.47, body extent -1.85,-3.35 1.85,3.35, height 1.8
"TE 282834-2" [mm]
  oval 1.75x2.5 hole 1.1: 1(-1.27,0) 2(1.27,0)
  silkscreen extent -2.7,-3.2 2.7,3.2, body extent -2.77,-3.25 2.77,3.25, height 10
"TE 282834-3" [mm]
  oval 1.75x2.5 hole 1.1: 1(-2.54,0) 2(0,0) 3(2.54,0)
  silkscreen extent -3.97,-3.2 3.97,3.2, body extent -4.04,-3.25 4.04,3.25, height 10
TP06R [mm] "Testpoint, round, d=0.6mm"
  round 0.6 smd paste-1: 1(0,0)
"WURTH WS-SLSU 450404015514" [mm] "Right angle Slide Switch"
  rect 0.7x1.1 smd: 1(2.25,-2.05) 2(-0.75,-2.05) 3(-2.25,-2.05)
  rect 1x0.8 smd: M(-3.75,-1.15) M(-3.75,1.15) M(3.75,-1.15) M(3.75,1.15)
  round 0.9 hole 0.9 unplated: MH(-1.5,0) MH(1.5,0)
  silkscreen extent -3.35,-1.35 3.35,2.85, body extent -3.85,-2.25 3.85,2.88, height 1.4

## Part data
C1 C3 C4 C7 C12 C14 C17 C18 C23 C25 C26 C27 C28 C30 C33 C34 C35 C40 C41: library part CC0805JRX7R9BB104, "CAP CER 0.1UF 50V X7R 0805", Capacitance=100n, Device Package="0805 (2012 Metric)", manufacturer=Yageo, Operating Temperature="-55°C ~ 125°C", Supplier Part Number 1=311-1858-1-ND, Temperature Coefficient=X7R, Tolerance=±5%, Voltage - Rated=50V
C2: library part 08055C473KAT2A, "CAP CER 0.047UF 50V X7R 0805", Capacitance=47n, Device Package="0805 (2012 Metric)", manufacturer="AVX Corporation", Operating Temperature="-55°C ~ 125°C", Supplier Part Number 1=478-1391-1-ND, Temperature Coefficient=X7R, Tolerance=±10%, Voltage - Rated=50V
C5: library part C0603C159C5GACTU, "CAP CER 1.5PF 50V C0G/NP0 0603", Capacitance=1p5, Device Package="0603 (1608 Metric)", manufacturer=KEMET, Operating Temperature="-55°C ~ 125°C", Supplier Part Number 1=399-C0603C159C5GACTUCT-ND, Temperature Coefficient="C0G, NP0", Tolerance=±0.25pF, Voltage - Rated=50V
C6 C8 C9 C10 C13 C16 C19 C20 C36 C37 C42 C43: library part CL31A106KBHNNNE, "CAP CER 10UF 50V X5R 1206", Capacitance=10u, Device Package="1206 (3216 Metric)", manufacturer="Samsung Electro-Mechanics", Operating Temperature="-55°C ~ 85°C", Supplier Part Number 1=1276-2876-1-ND, Temperature Coefficient=X5R, Tolerance=±10%, Voltage - Rated=50V
C11 C21: library part CC0603KRX7R9BB333, "CAP CER 0.033UF 50V X7R 0603", Capacitance=33n, Device Package="0603 (1608 Metric)", manufacturer=Yageo, Operating Temperature="-55°C ~ 125°C", Supplier Part Number 1=311-1429-1-ND, Temperature Coefficient=X7R, Tolerance=±10%, Voltage - Rated=50V
C15: library part GRM32ER71A476KE15L, "CAP CER 47UF 10V X7R 1210", Capacitance="47 µF", Device Package="1210 (3225 Metric)", manufacturer="Murata Electronics", Operating Temperature="-55°C ~ 125°C", Supplier Part Number 1=490-5312-1-ND, Temperature Coefficient=X7R, Tolerance=±10%, Voltage - Rated=10V
C22 C29: library part EMK107B7105KA-T, "CAP CER 1UF 16V X7R 0603", Capacitance=1u, Device Package="0603 (1608 Metric)", manufacturer="Taiyo Yuden", Operating Temperature="-55°C ~ 125°C", Supplier Part Number 1=587-1241-1-ND, Temperature Coefficient=X7R, Tolerance=±10%, Voltage - Rated=16V
C24: library part GRM31CR71H475KA12L, "CAP CER 4.7UF 50V X7R 1206", Capacitance=4u7, Device Package="1206 (3216 Metric)", manufacturer="Murata Electronics", Operating Temperature="-55°C ~ 125°C", Supplier Part Number 1=490-6521-1-ND, Temperature Coefficient=X7R, Tolerance=±10%, Voltage - Rated=50V
C31 C32: library part CC0402CRNPO9BN9R0, "CAP CER 9PF 50V C0G/NPO 0402", Capacitance=9p, Device Package="0402 (1005 Metric)", manufacturer=Yageo, Operating Temperature="-55°C ~ 125°C", Supplier Part Number 1=311-1636-1-ND, Temperature Coefficient="C0G, NP0", Tolerance=±0.25pF, Voltage - Rated=50V
C38 C39 C44 C45: library part GRM155R70J105KA12J, "CAP CER 1UF 6.3V X7R 0402", Capacitance=1u, Device Package="0402 (1005 Metric)", manufacturer="Murata Electronics", Operating Temperature="-55°C ~ 125°C", Supplier Part Number 1=490-13339-1-ND, Temperature Coefficient=X7R, Tolerance=±10%, Voltage - Rated=6.3V
D1 D2 D3 D4: library part 5988170107F, "LED GREEN CLEAR 0805 SMD", Current - Test=20mA, Device Package="0805 (2012 Metric)", Lens Color=Colorless, manufacturer=Dialight, Millicandela Rating=20mcd, Supplier Device Package=0805, Supplier Part Number 1=350-2044-1-ND, Voltage - Forward (Vf) (Typ)=2V
D5: "TVS DIODE 28VWM 45.4VC DO214AA", Current - Peak Pulse (10/1000µs)=13.3A, manufacturer="Littelfuse Inc.", Operating Temperature="-65°C ~ 150°C (TJ)", Package / Case="DO-214AA, SMB", Power - Peak Pulse=600W, Power Line Protection=No, Supplier Device Package="DO-214AA (SMBJ)", Supplier Part Number 1=SMBJ28CALFCT-ND, Voltage - Breakdown (Min)=31.1V, Voltage - Clamping (Max) @ Ipp=45.4V, Voltage - Reverse Standoff (Typ)=28V
D6 D7: "DIODE ZENER 3.9V 365MW SOD123W", Current - Reverse Leakage @ Vr="3 µA @ 1 V", manufacturer="Nexperia USA Inc.", Operating Temperature="150°C (TJ)", Package / Case=SOD-123, Power - Max="365 mW", Supplier Device Package=SOD-123W, Supplier Part Number 1=1727-7706-1-ND, Tolerance=±2%, Voltage - Forward (Vf) (Max) @ If="1.1 V @ 100 mA", Voltage - Zener (Nom) (Vz)="3.9 V"
D8 D9: "TVS DIODE 3.6VWM 6.8VC 2X1SON", Capacitance @ Frequency="0.9pF @ 1MHz", Current - Peak Pulse (10/1000µs)="6A (8/20µs)", Device Package="0402 (1005 Metric)", manufacturer="Texas Instruments", Operating Temperature="-40°C ~ 125°C (TA)", Power - Peak Pulse=40W, Power Line Protection=No, Supplier Device Package="2-X1SON (1x.60)", Supplier Part Number 1=296-51108-1-ND, Voltage - Breakdown (Min)=4.5V, Voltage - Clamping (Max) @ Ipp="6.8V (Typ)", Voltage - Reverse Standoff (Typ)="3.6V (Max)"
D10: "TVS DIODE 5.5VWM 14VC 2X1SON", Current - Peak Pulse (10/1000µs)="5A (8/20µs)", Device Package="0402 (1005 Metric)", manufacturer="Texas Instruments", Operating Temperature="-40°C ~ 125°C (TA)", Power - Peak Pulse=90W, Power Line Protection=No, Supplier Device Package="2-X1SON (1x.60)", Supplier Part Number 1=296-30406-1-ND, Voltage - Breakdown (Min)=6V, Voltage - Clamping (Max) @ Ipp=14V, Voltage - Reverse Standoff (Typ)="5.5V (Max)"
FD1 FD2 FD3: library part CMP-00028-00005-4, "Fiducial - Round 1x2mm"
IC1 IC2: library part CMP-031-00008-1, "Integrated Circuit", Manufacturer_Name="Texas Instruments", Mouser Part Number=595-DRV10975ZPWPR
J1: library part CMP-15126-126517171-1, "20021121-00010C4LF Conn Unshrouded Header HDR 10 POS 1.27mm Solder ST Top Entry SMD Minitek127® T/R", Color=Black, Contact Resistance=30mΩ, Current Rating=1A, Insulation Resistance=100MΩ, Max Operating Temperature=85°C, Max Voltage Rating (AC)=125V, Min Operating Temperature=-55°C
J2 J4 J6: "TERM BLK 3P SIDE ENT 2.54MM PCB", Color=Green, Current=10A, manufacturer="TE Connectivity AMP Connectors", Supplier Part Number 1=A98334-ND, Voltage=150V
J3: "TERM BLK 2P SIDE ENT 2.54MM PCB", Color=Green, Current=10A, manufacturer="TE Connectivity AMP Connectors", Supplier Part Number 1=A98333-ND, Voltage=150V
J5: "CONN RCPT USB 2.0 TYPE C SMD RA", Current Rating (Amps)="0.25A, 1.25A, 5A", manufacturer="Same Sky (Formerly CUI Devices)", Operating Temperature="-25°C ~ 85°C", Supplier Part Number 1=2223-UJ20-C-H-G-SMT-2-P16-TRCT-ND
J7 J8: library part CMP-17439-000233-1, "CONN HEADER SMD 7POS 2MM", Color=White, Contact Resistance=20mR, Current Rating=2A, Flammability Rating="UL94 V-0", Housing Color=Beige, Insulation Color=Natural, Insulation Resistance=1GR, Max Operating Temperature=85°C, Max Voltage Rating (AC)=100V, Min Operating Temperature=-25°C
L1: library part CMP-006-00025-2, "Inductor Power Unshielded Wirewound 12uH 20% 100KHz 25Q-Factor Ferrite 4.8A 0.03Ohm DCR T/R", Case/Package=Nonstandard, Current Rating=4.8A, DC Resistance (DCR)=30mΩ, Inductance Tolerance=20%, Manufacturer_Name=Bourns, Max Operating Temperature=125°C, Min Operating Temperature=-40°C, Mouser Part Number=652-SDR1307-120ML, Saturation Current=8A, Self Resonant Frequency=20MHz, Test Frequency=100kHz
L2: library part CMP-006-00024-1, "Inductor Power Shielded Wirewound 8.2uH 20% 100KHz Powdered Iron 9.5A 0.0225Ohm DCR 5050 T/R", Case/Package=5050, Current Rating=9.5A, DC Resistance (DCR)=22.5mΩ, Inductance Tolerance=20%, Max Operating Temperature=125°C, Min Operating Temperature=-55°C, Saturation Current=18A, Test Frequency=100kHz
Q1: library part CMP-12801-000088-1, "MOSFET BVDSS: 41V-60V POWERDI333", Continuous Drain Current (ID)=80A, Drain to Source Voltage (Vdss)=60V, Input Capacitance=2.09nF, Max Operating Temperature=150°C, Max Power Dissipation=62.5W, Min Operating Temperature=-55°C
Q2: library part CMP-07173-000101-1, "MOSFET N-CH 50V 220MA SOT-23", Case/Package=SOT-23, Continuous Drain Current (ID)=220mA, Drain to Source Breakdown Voltage=50V, Drain to Source Resistance=3.5R, Gate to Source Voltage (Vgs)=20V, Input Capacitance=27pF, Max Operating Temperature=150°C, Max Power Dissipation=360mW, Min Operating Temperature=-55°C, On-State Resistance=6R, Package Quantity=1, Threshold Voltage=1.3V
R1: library part RC0603JR-1322KL, "RES 22K OHM 5% 1/10W 0603", Device Package="0603 (1608 Metric)", manufacturer=Yageo, Operating Temperature="-55°C ~ 155°C", Power (Watts)="0.1W, 1/10W", Resistance="22 kOhms", Supplier Device Package=0603, Supplier Part Number 1=13-RC0603JR-1322KLCT-ND, Temperature Coefficient=±100ppm/°C, Tolerance=±5%
R2 R6 R8 R12 R13 R14 R15 R16 R22 R28: library part CRCW060310K0FKEA, "RES SMD 10K OHM 1% 1/10W 0603", Device Package="0603 (1608 Metric)", manufacturer="Vishay Dale", Operating Temperature="-55°C ~ 155°C", Power (Watts)="0.1W, 1/10W", Ratings=AEC-Q200, Resistance="10 kOhms", Supplier Device Package=0603, Supplier Part Number 1=541-10.0KHCT-ND, Temperature Coefficient=±100ppm/°C, Tolerance=±1%
R3: library part RC0603JR-134K7L, "RES 4.7K OHM 5% 1/10W 0603", Device Package="0603 (1608 Metric)", manufacturer=Yageo, Operating Temperature="-55°C ~ 155°C", Power (Watts)="0.1W, 1/10W", Resistance="4.7 kOhms", Supplier Device Package=0603, Supplier Part Number 1=13-RC0603JR-134K7LCT-ND, Temperature Coefficient=±100ppm/°C, Tolerance=±5%
R4: library part RC0603JR-132K2L, "RES 2.2K OHM 5% 1/10W 0603", Device Package="0603 (1608 Metric)", manufacturer=Yageo, Operating Temperature="-55°C ~ 155°C", Power (Watts)="0.1W, 1/10W", Resistance="2.2 kOhms", Supplier Device Package=0603, Supplier Part Number 1=13-RC0603JR-132K2LCT-ND, Temperature Coefficient=±100ppm/°C, Tolerance=±5%
R5: library part CRCW0603115KFKEA, "RES SMD 115K OHM 1% 1/10W 0603", Device Package="0603 (1608 Metric)", manufacturer="Vishay Dale", Operating Temperature="-55°C ~ 155°C", Power (Watts)="0.1W, 1/10W", Ratings=AEC-Q200, Resistance="115 kOhms", Supplier Device Package=0603, Supplier Part Number 1=541-115KHCT-ND, Temperature Coefficient=±100ppm/°C, Tolerance=±1%
R7: library part RC0603FR-0752K3L, "RES 52.3K OHM 1% 1/10W 0603", Device Package="0603 (1608 Metric)", manufacturer=Yageo, Operating Temperature="-55°C ~ 155°C", Power (Watts)="0.1W, 1/10W", Resistance="52.3 kOhms", Supplier Device Package=0603, Supplier Part Number 1=311-52.3KHRCT-ND, Temperature Coefficient=±100ppm/°C, Tolerance=±1%
R9: library part CRGCQ0603J33K, "RES 33K OHM 5% 1/10W 0603", Device Package="0603 (1608 Metric)", manufacturer="TE Connectivity Passive Product", Operating Temperature="-55°C ~ 155°C", Power (Watts)="0.1W, 1/10W", Ratings=AEC-Q200, Resistance="33 kOhms", Supplier Device Package=0603, Supplier Part Number 1=A130100CT-ND, Temperature Coefficient=±100ppm/°C, Tolerance=±5%
R10: library part RC0603FR-1082KL, "RES 82K OHM 1% 1/10W 0603", Device Package="0603 (1608 Metric)", manufacturer=Yageo, Operating Temperature="-55°C ~ 155°C", Power (Watts)="0.1W, 1/10W", Resistance="82 kOhms", Supplier Device Package=0603, Supplier Part Number 1=13-RC0603FR-1082KLCT-ND, Temperature Coefficient=±100ppm/°C, Tolerance=±1%
R11: library part RC0603FR-07100RL, "RES 100 OHM 1% 1/10W 0603", Device Package="0603 (1608 Metric)", manufacturer=Yageo, Operating Temperature="-55°C ~ 155°C", Power (Watts)="0.1W, 1/10W", Resistance="100 Ohms", Supplier Device Package=0603, Supplier Part Number 1=311-100HRCT-ND, Temperature Coefficient=±100ppm/°C, Tolerance=±1%
R17 R18 R23 R24: library part CRCW080578R7FKEA, "RES SMD 78.7 OHM 1% 1/8W 0805", Device Package="0805 (2012 Metric)", manufacturer="Vishay Dale", Operating Temperature="-55°C ~ 155°C", Power (Watts)="0.125W, 1/8W", Ratings=AEC-Q200, Resistance="78.7 Ohms", Supplier Device Package=0805, Supplier Part Number 1=541-78.7CCT-ND, Temperature Coefficient=±100ppm/°C, Tolerance=±1%
R19 R20 R21 R25 R26 R27: library part RMCF0603FT4K75, "RES 4.75K OHM 1% 1/10W 0603", Device Package="0603 (1608 Metric)", manufacturer="Stackpole Electronics Inc", Operating Temperature="-55°C ~ 155°C", Power (Watts)="0.1W, 1/10W", Ratings=AEC-Q200, Resistance="4.75 kOhms", Supplier Device Package=0603, Supplier Part Number 1=RMCF0603FT4K75CT-ND, Temperature Coefficient=±100ppm/°C, Tolerance=±1%
R29 R30: library part RMCF0603JT5K10, "RES 5.1K OHM 5% 1/10W 0603", Device Package="0603 (1608 Metric)", manufacturer="Stackpole Electronics Inc", Operating Temperature="-55°C ~ 155°C", Power (Watts)="0.1W, 1/10W", Ratings=AEC-Q200, Resistance="5.1 kOhms", Supplier Device Package=0603, Supplier Part Number 1=RMCF0603JT5K10CT-ND, Temperature Coefficient=±200ppm/°C, Tolerance=±5%
S1: "MINI SLIDE SWITCH 6.7 X 2.7 MM.", Current Rating (Amps)="300mA (DC)", manufacturer="Würth Elektronik", Operating Temperature="-40°C ~ 85°C", Rated Current=300mA, Rated Voltage=5VDC, Supplier Part Number 1=732-13665-1-ND, Voltage Rating - DC="5 V"
ST1 ST2 ST3 ST4: library part CMP-00028-00007-3, "M4 PTH (4.5mm), 7.5mm pad"
TP1 TP2 TP3 TP4 TP5 TP6 TP7 TP8 TP9 TP10 TP11 TP12 TP13 TP14 TP15 TP16 TP17 TP18 TP19 TP20 TP21 TP22 TP23 TP24 TP25 TP26 TP27 TP28 TP29 TP30 TP31 TP32 TP33 TP34 TP35 TP36 TP37 TP38 TP39: library part CMP-00028-00002-3, "0.6mm round"
U1 U3: library part CMP-04918-000610-1, "3.8-V to 30-V, 3-A, 200-kHz to 2.2-MHz, low-IQ synchronous buck converter in SOT-583 package 8-SOT-5X3 -40 to 150"
U2: library part CMP-04910-000003-1, "POWER MANAGEMENT", Ambient Temperature Range High=+125°C, Ambient Temperature Range Low=-40°C, manufacturer="Texas Instruments", Max Junction Temp=+150°C, Max Supply Voltage=65V, Min Supply Voltage=3.2V, Nominal Supply Current=80uA, Package=DBV0006A, Temperature="-40°C to +125°C"
U4: library part CMP-0136-00458-1, "500 mA, Low Voltage, Low Quiescent Current LDO Regulator, 3-Pin SOT-223, Extended Temperature"
U5: library part CMP-12105-000150-1, "IC MCU 32BIT 128KB FLASH 64LQFP"
Y1: library part CMP-003-00030-1, "Crystal 24MHz ±10ppm (Tol) ±20ppm (Stability) 8pF FUND 50Ohm 4-Pin SMD T/R", ESR (Equivalent Series Resistance)=50Ω, Frequency=24MHz, Frequency Stability=20ppm, Frequency Tolerance=0.001%, Load Capacitance=8pF, Max Operating Temperature=85°C, Min Operating Temperature=-40°C

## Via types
v1: diameter 0.55, hole 0.35, L1 (Signal) to L6 (Signal), tented both sides, 219 vias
